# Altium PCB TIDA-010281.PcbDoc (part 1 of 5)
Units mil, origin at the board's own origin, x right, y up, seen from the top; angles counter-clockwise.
Board outline 3455.86 x 1121.8 mil, 8 copper layers (Top Layer, GND1, Sig1, PWR1, PWR2, Sig2, GND2, Bottom Layer), stack 59.155 mil thick; 291 components, 180 nets, 941 pads, 539 vias.
Unrouted connection lines stored in the file: 41.
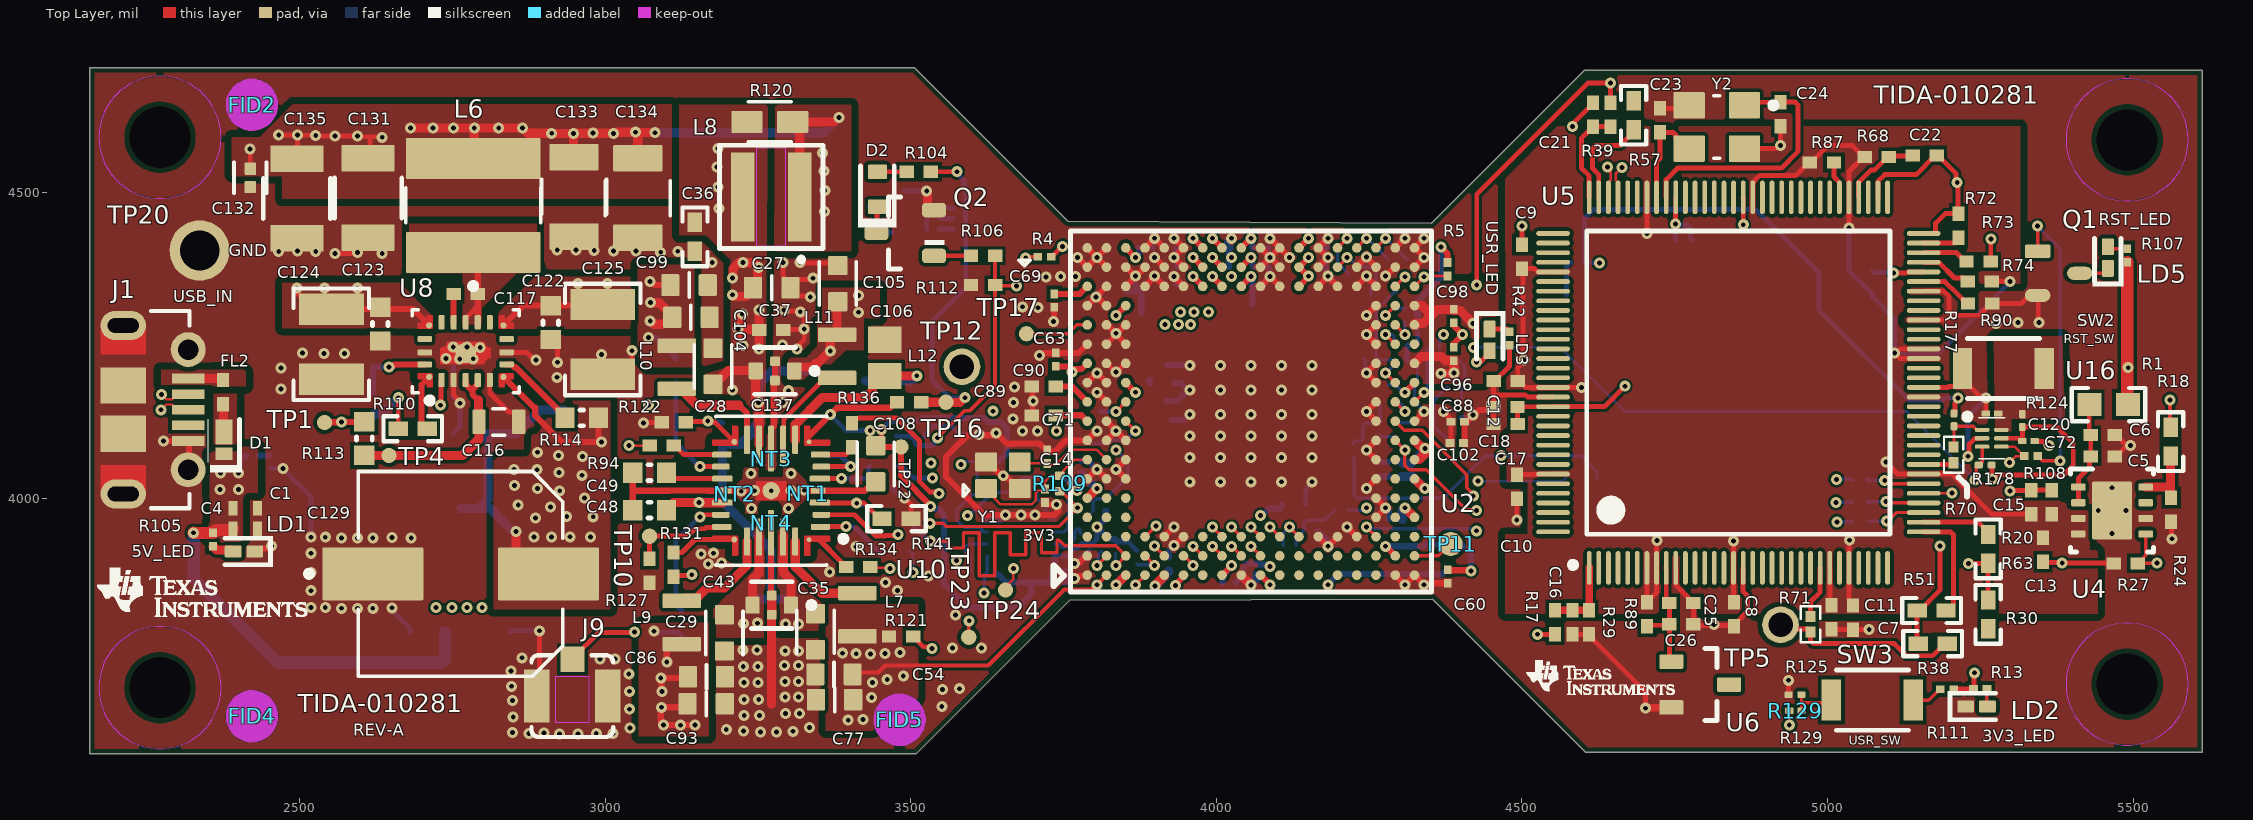
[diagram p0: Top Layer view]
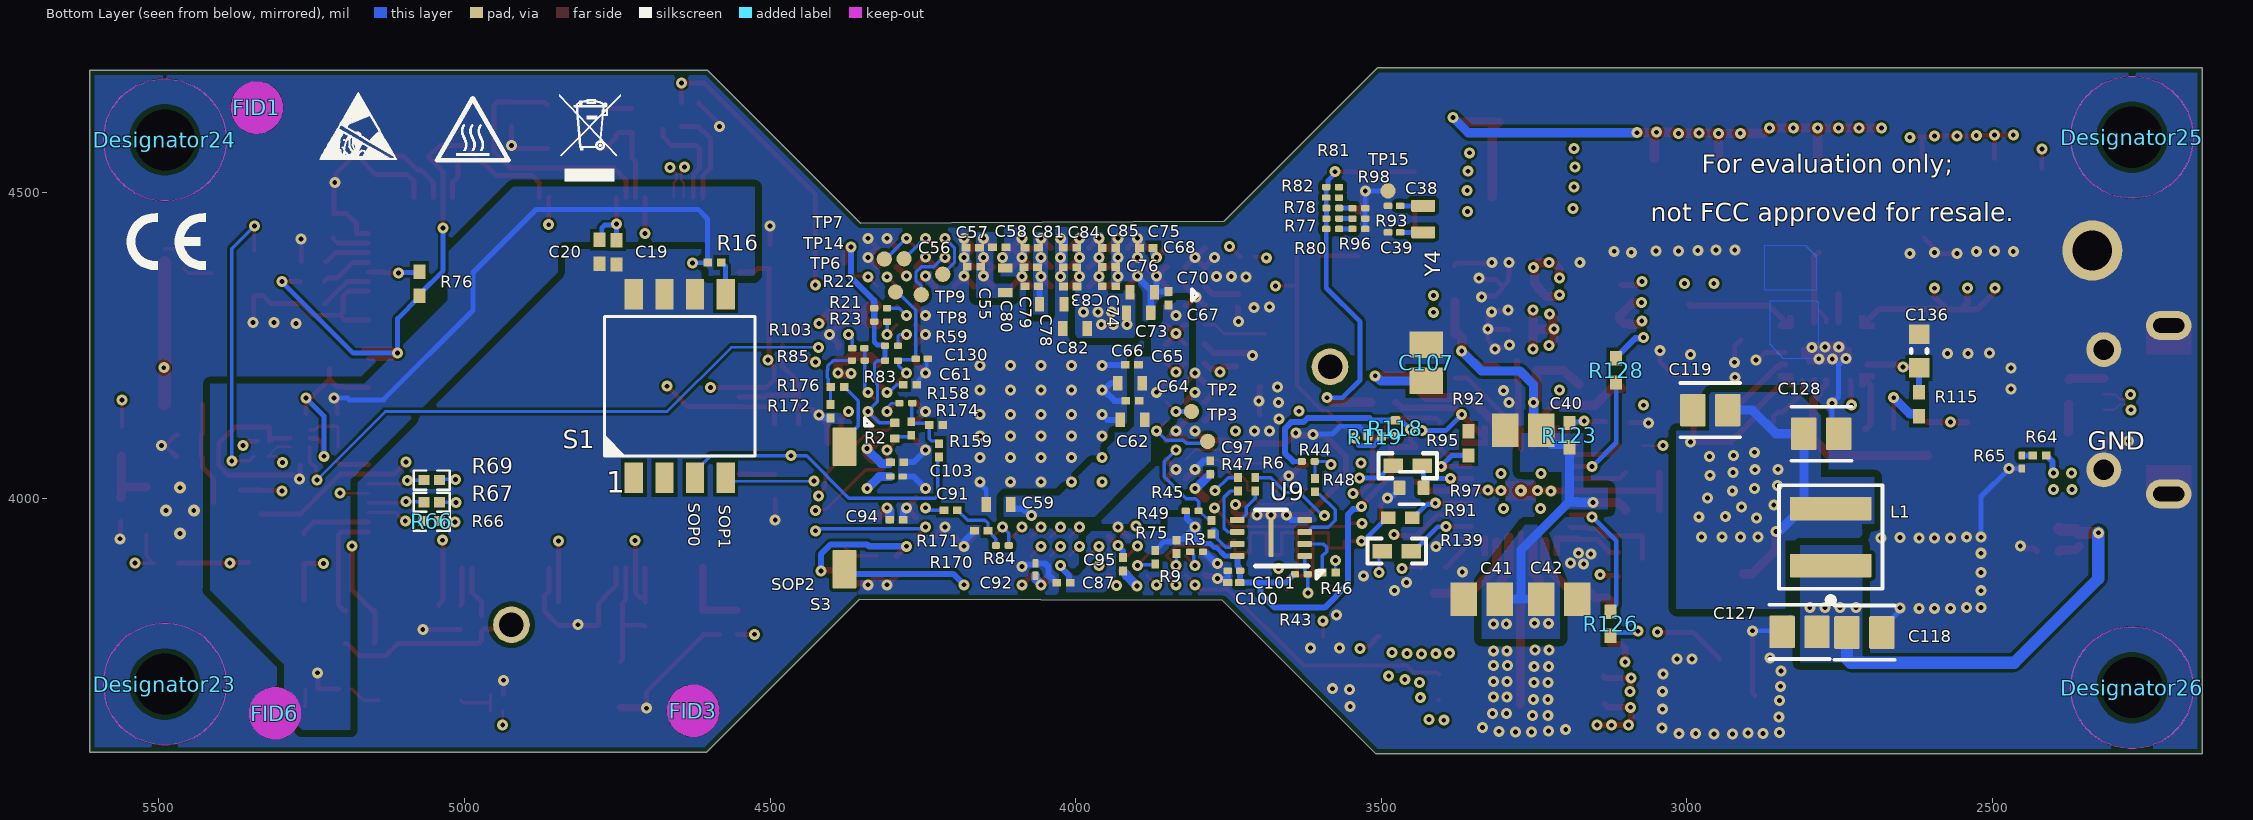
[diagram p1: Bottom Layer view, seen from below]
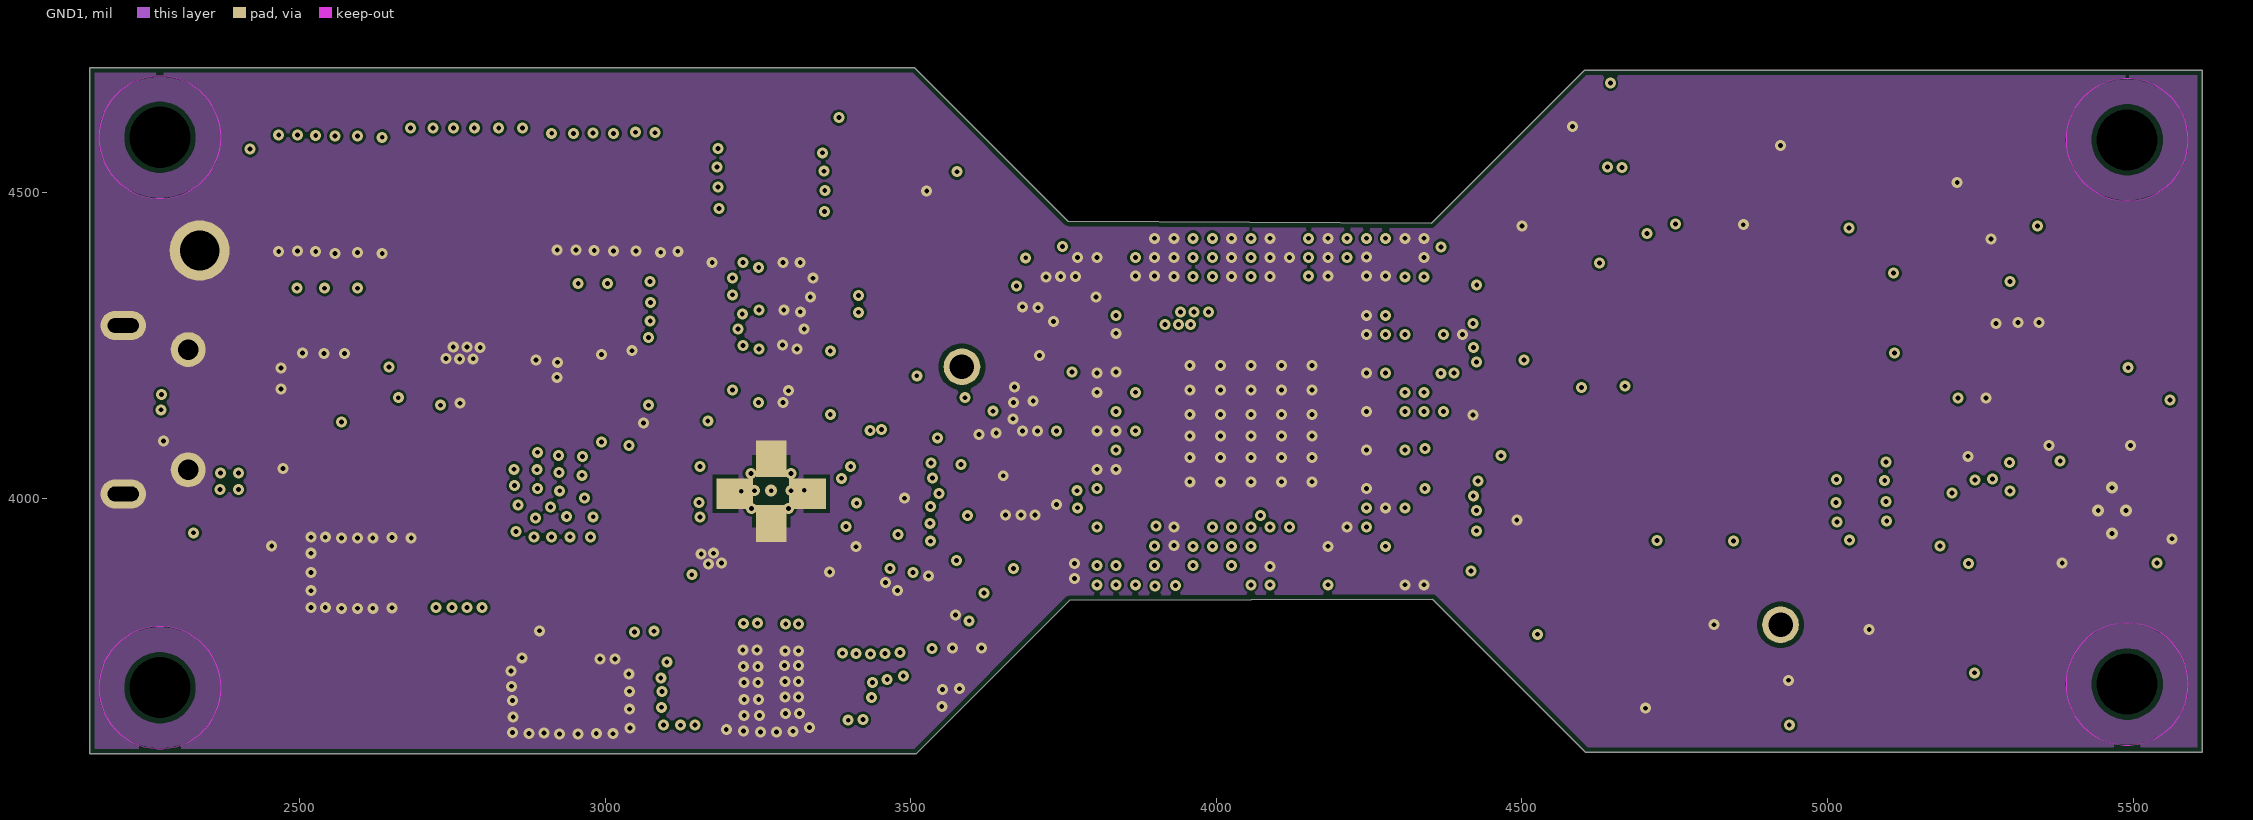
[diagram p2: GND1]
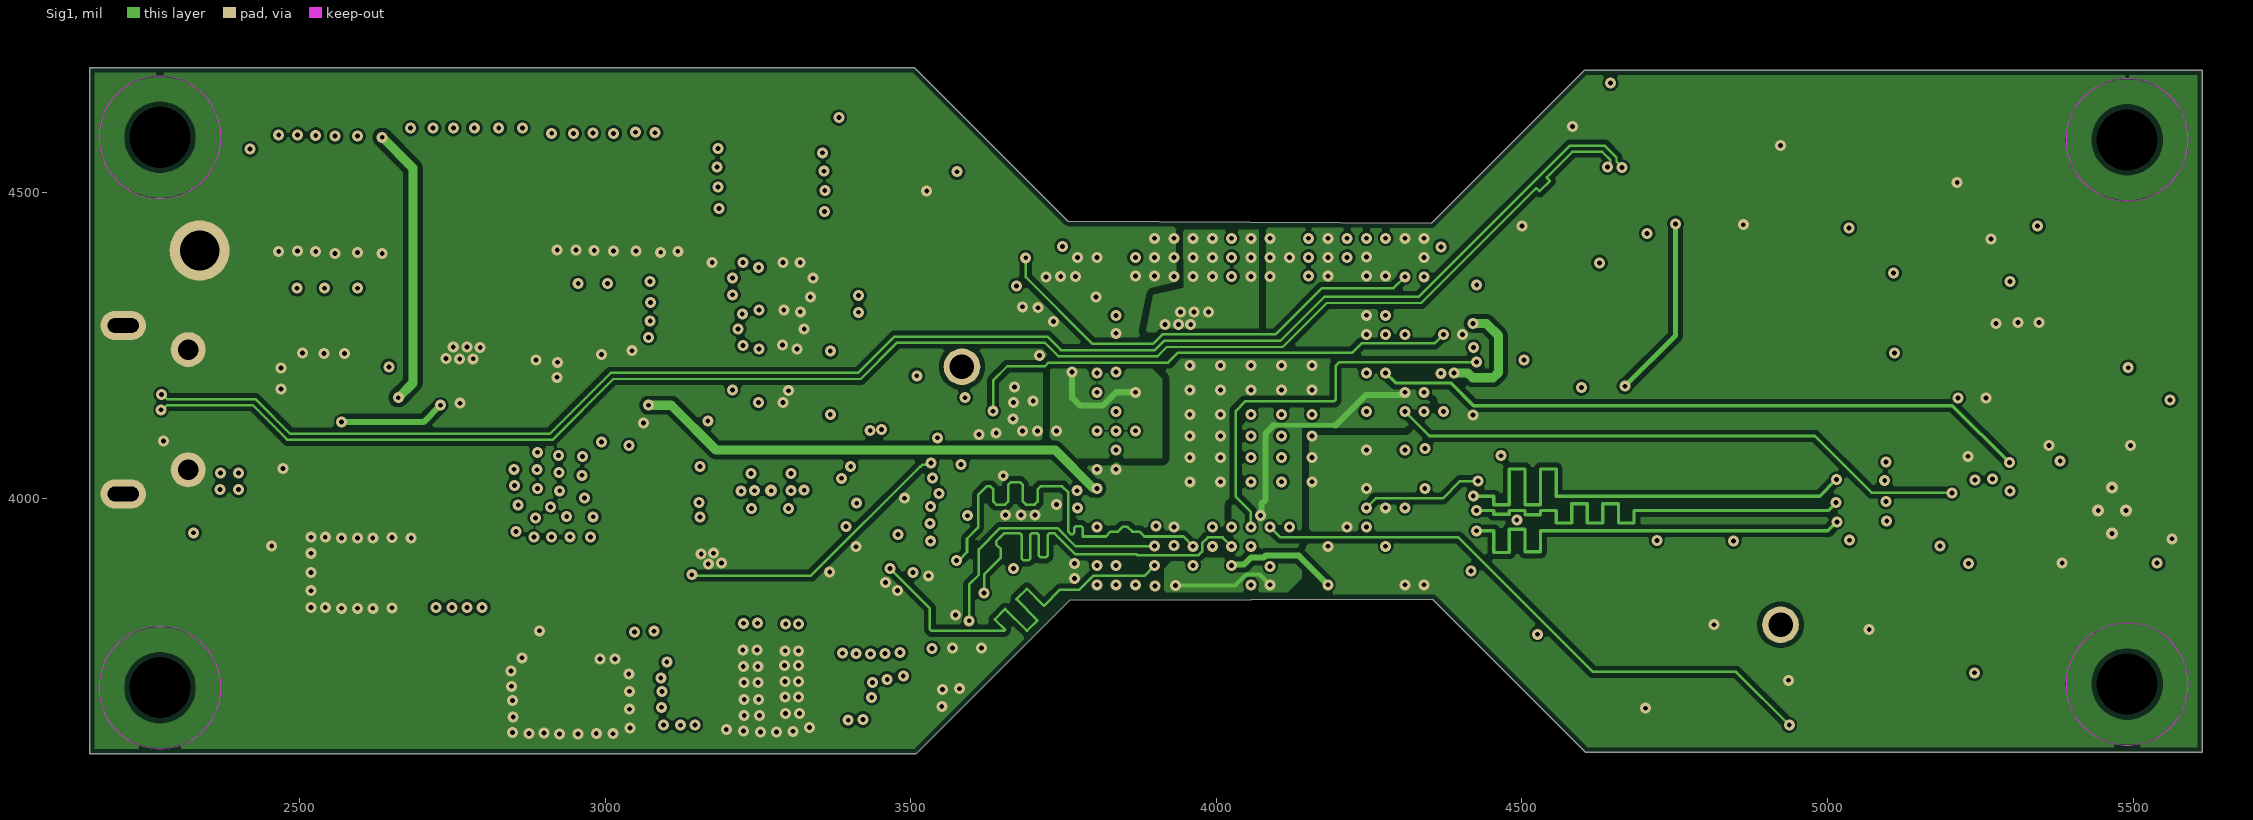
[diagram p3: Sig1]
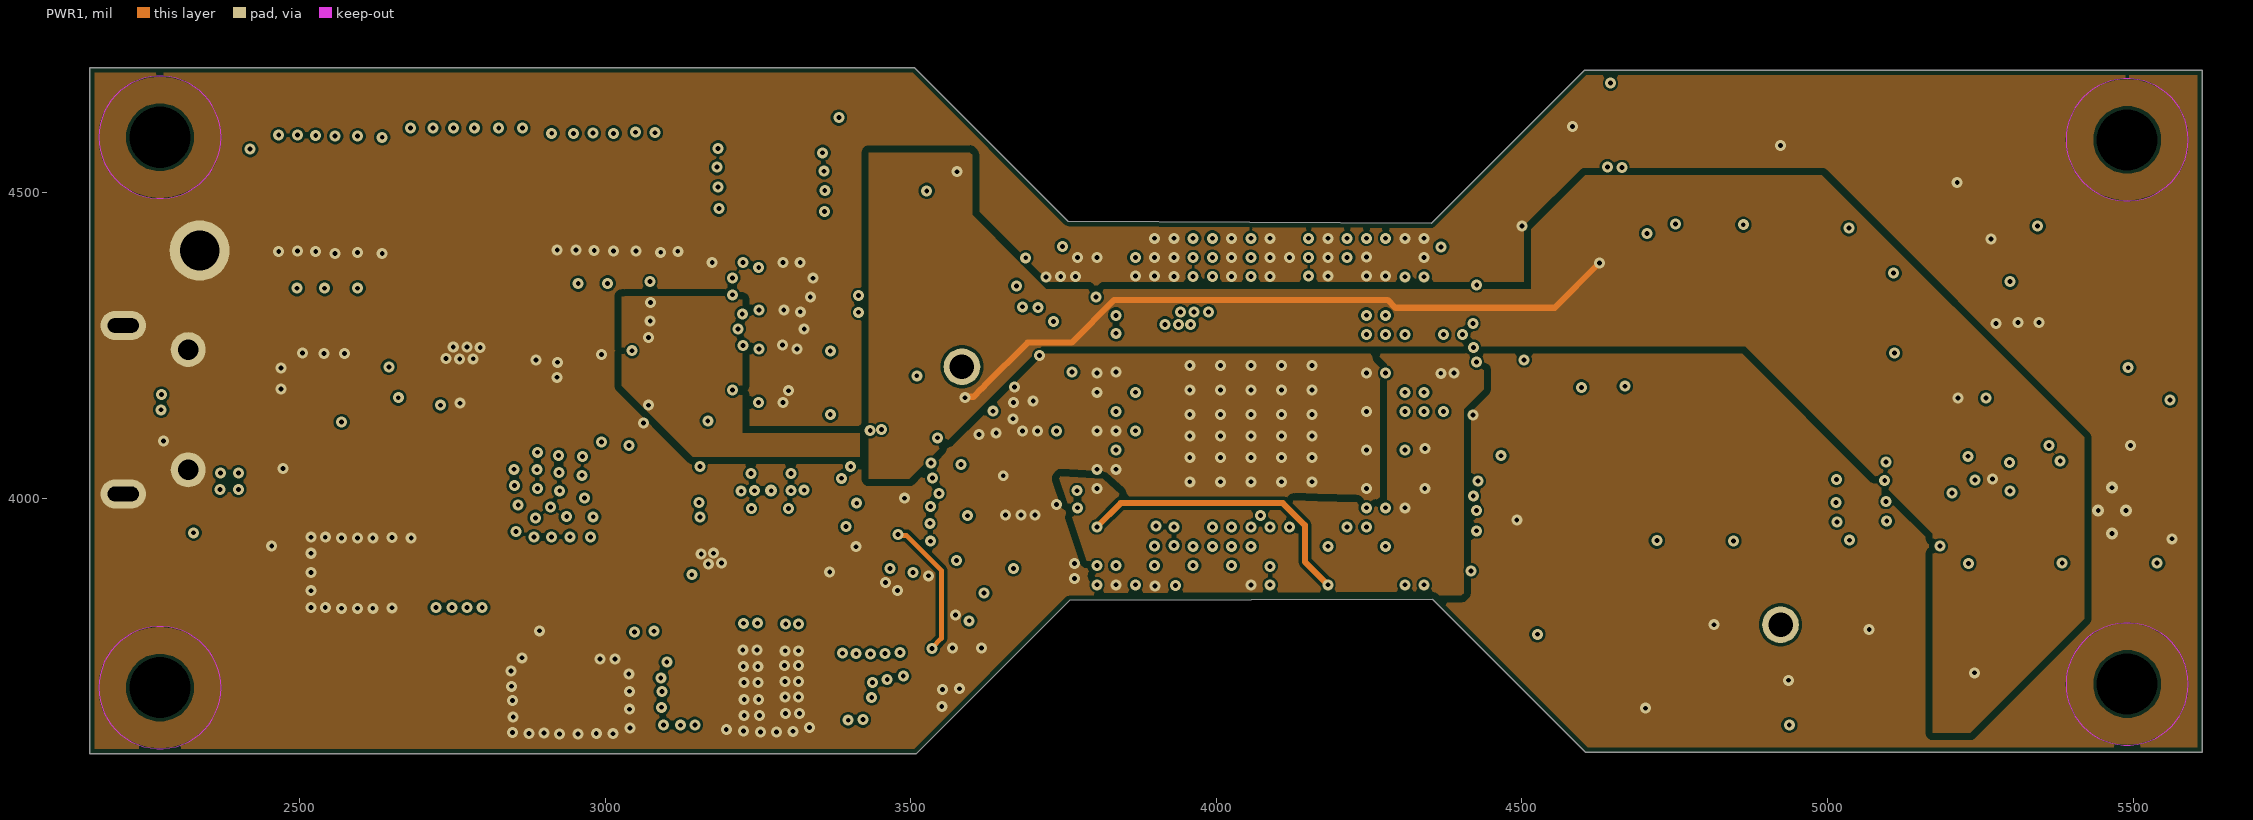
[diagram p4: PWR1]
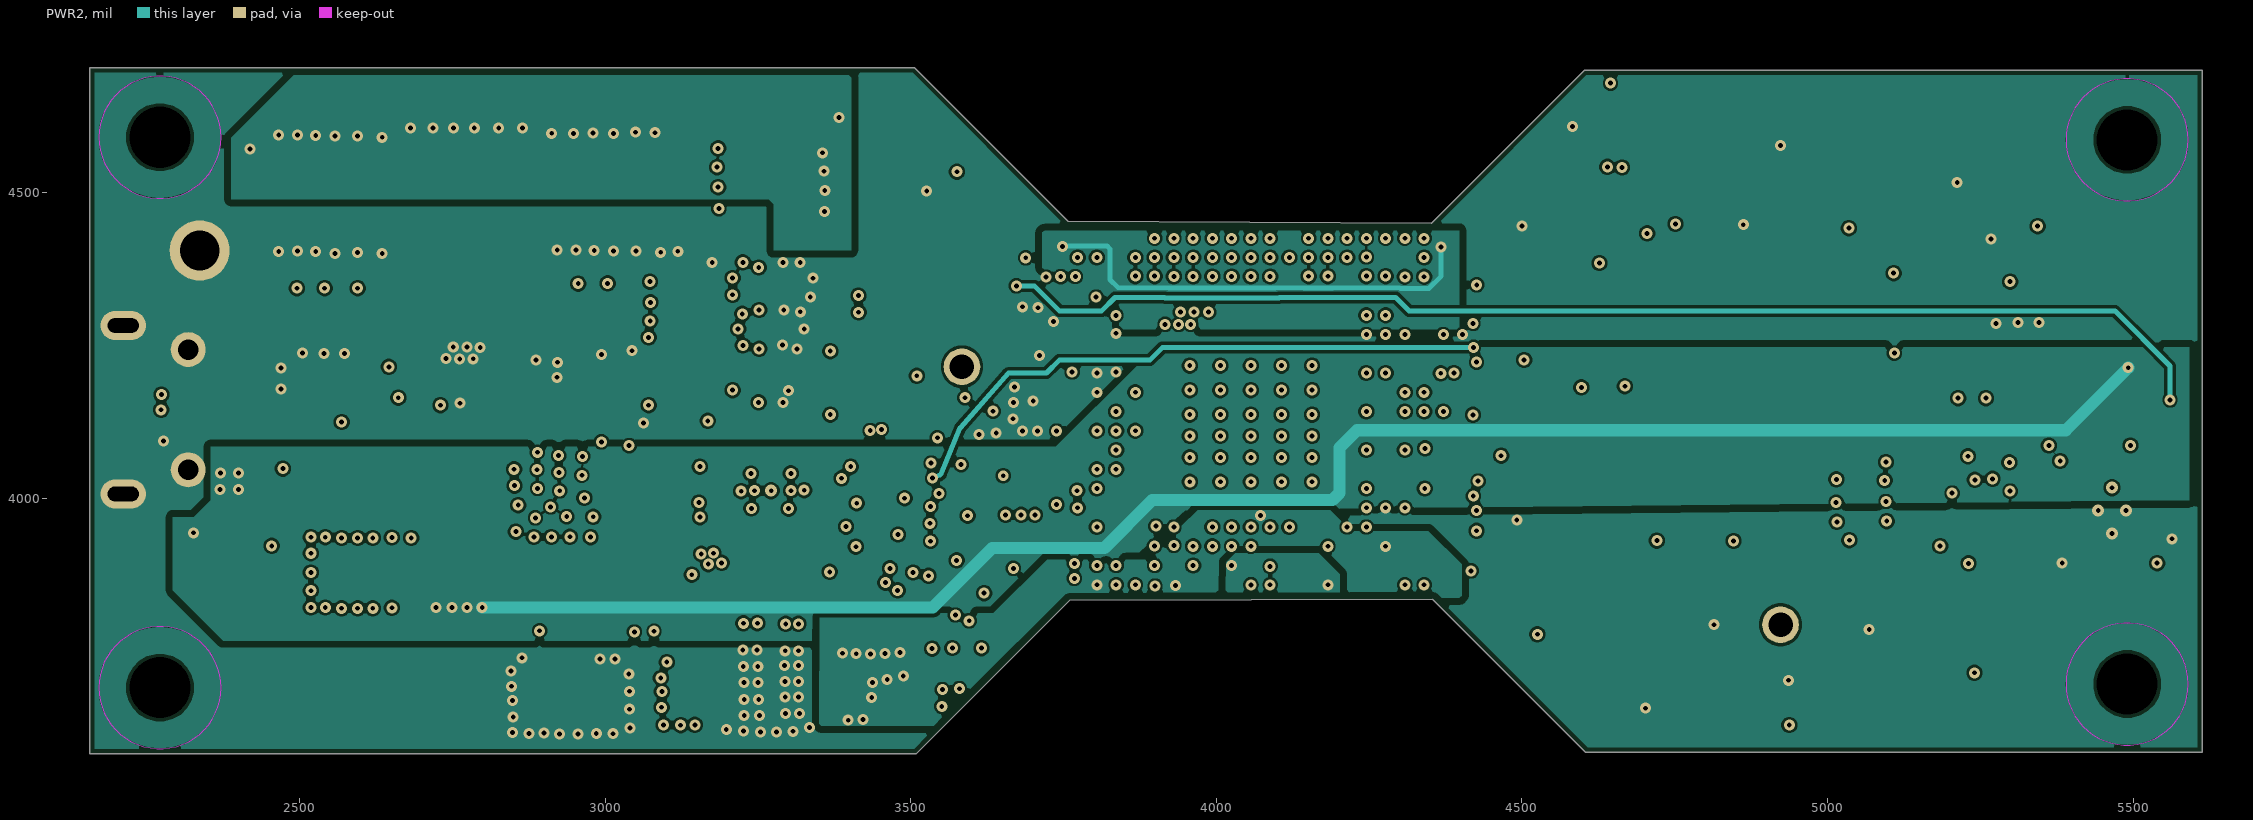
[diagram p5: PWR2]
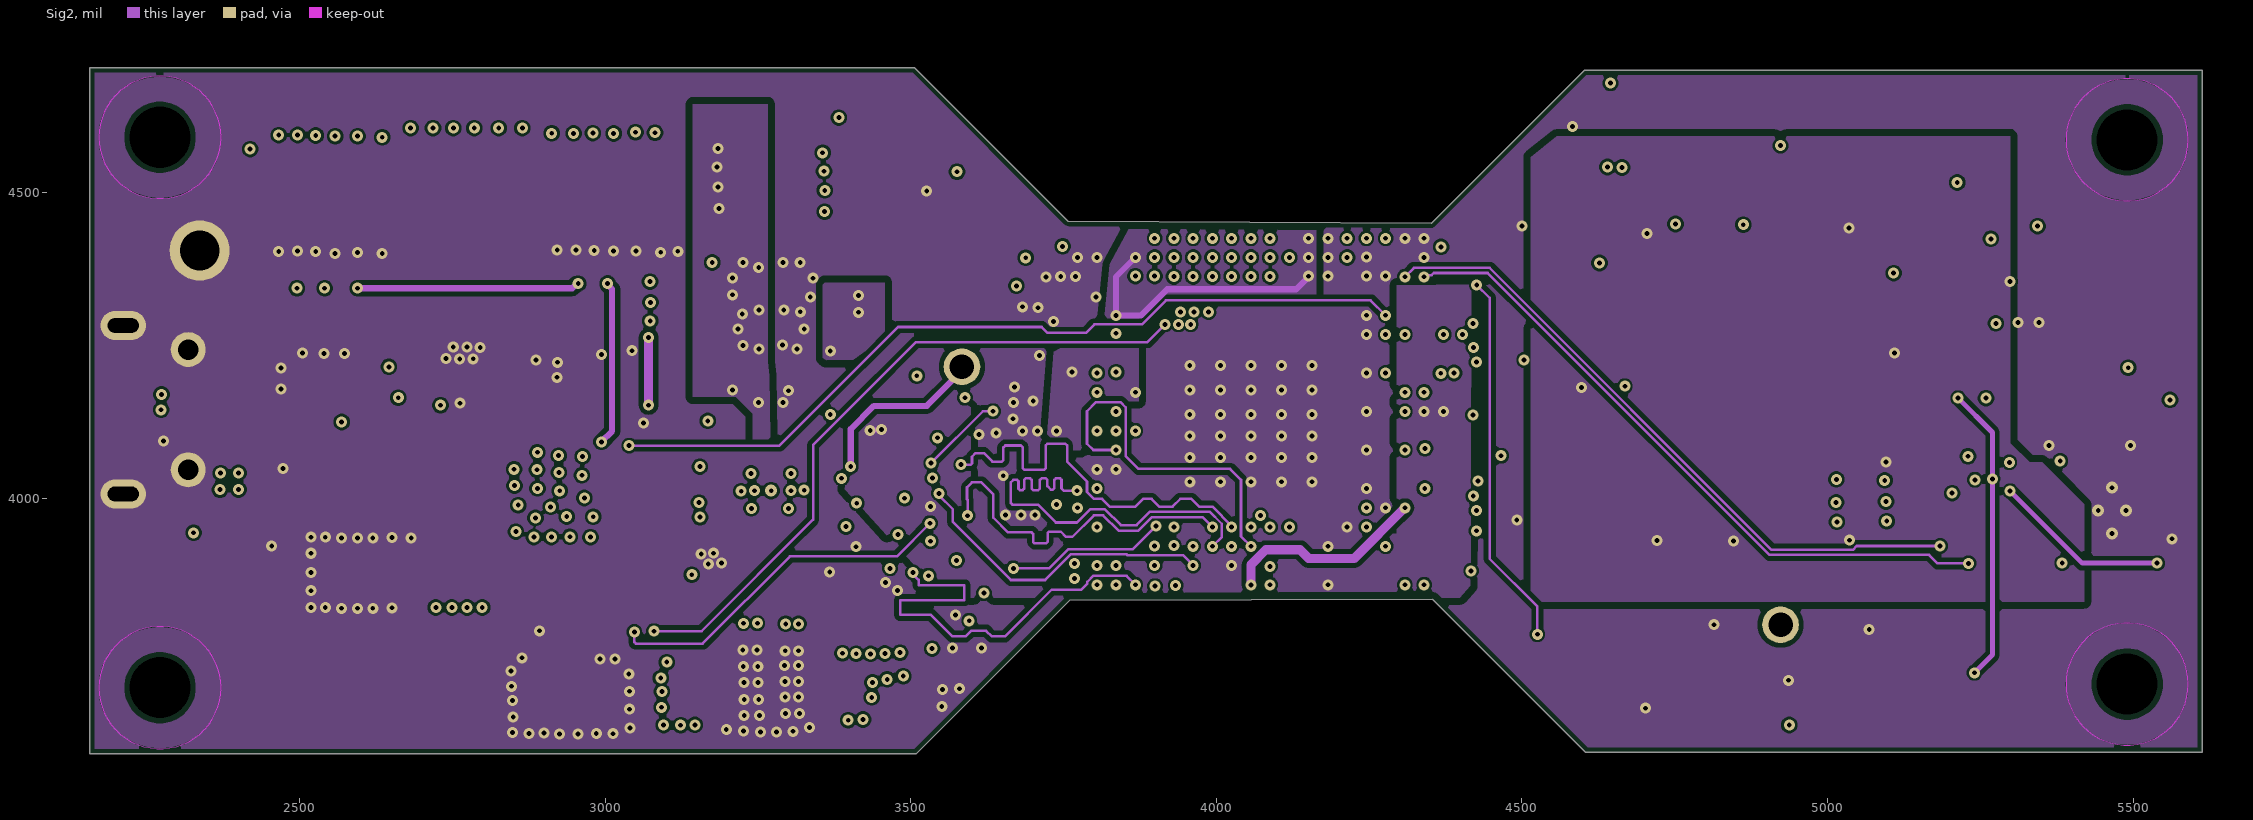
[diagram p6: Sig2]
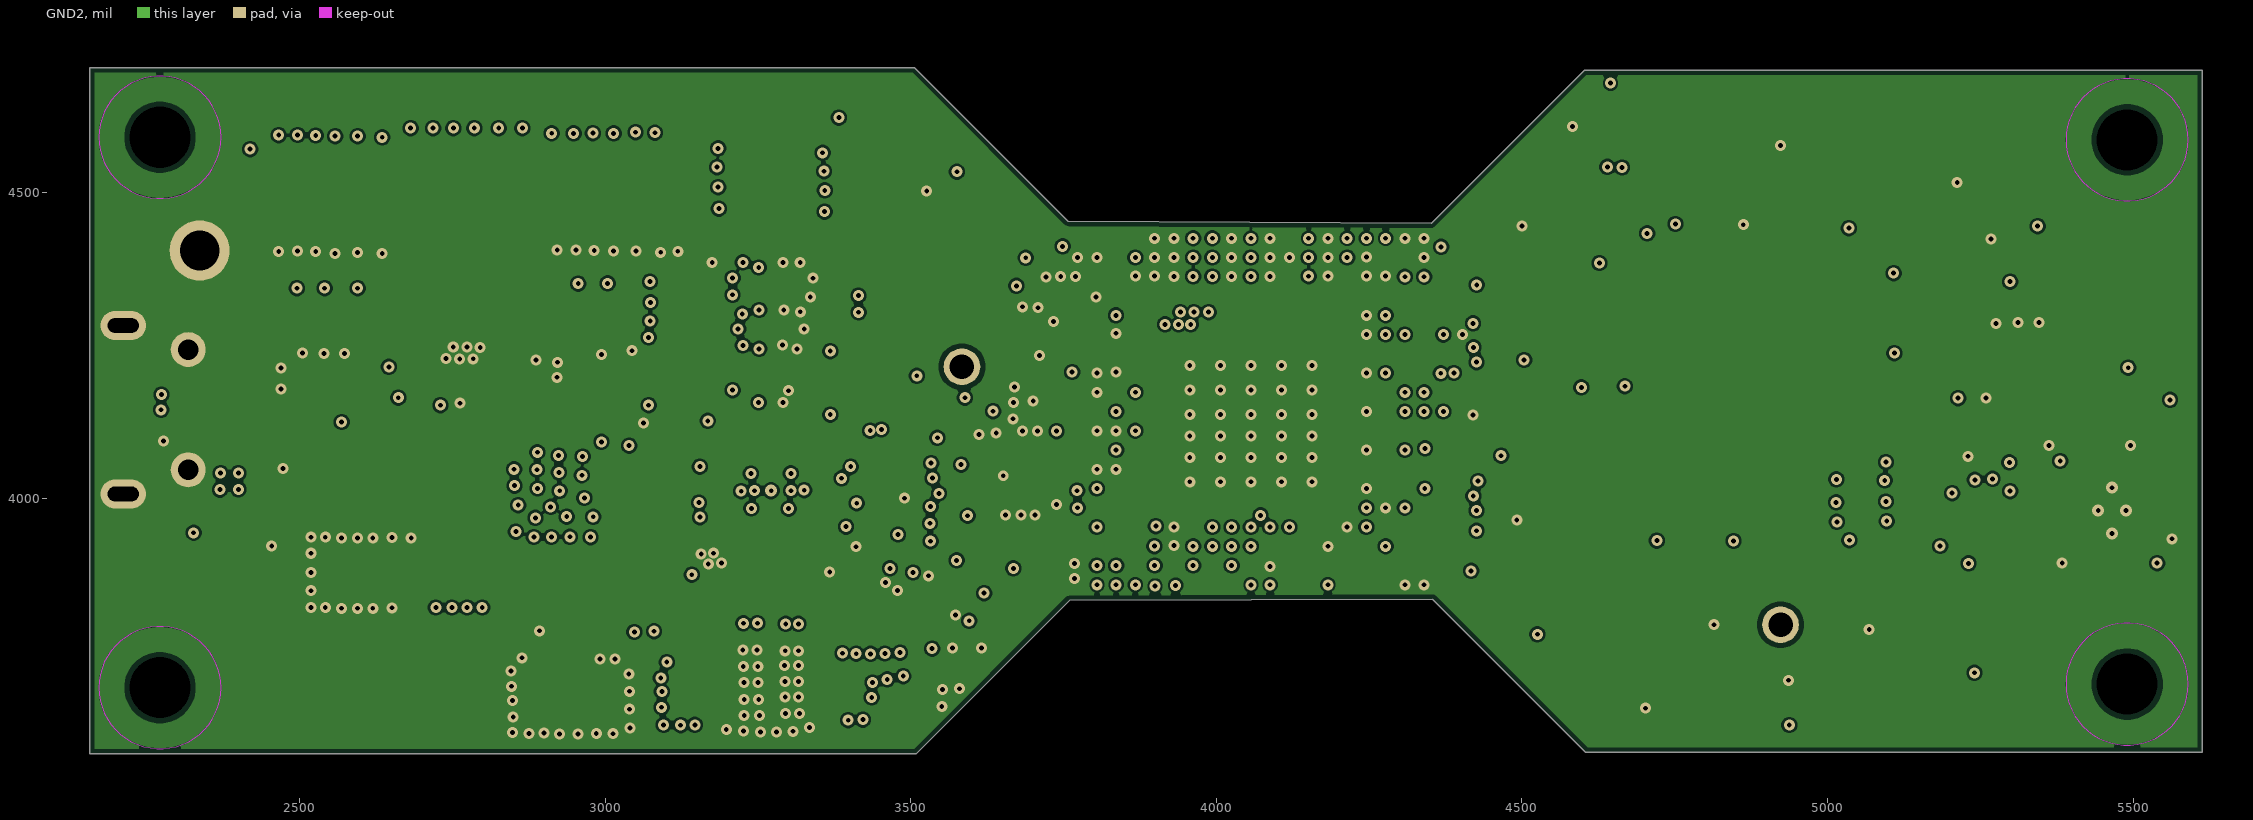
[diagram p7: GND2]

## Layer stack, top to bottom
Top Solder: solder mask 2, Solder Resist, Dk 4.4
Top Layer: signal copper 1.85
Dielectric1: core 1.462, FR-4 High Tg, Dk 3.832
Dielectric 2: core 2.224, FR-4 High Tg, Dk 3.832
GND1: signal copper 2.638
Dielectric3: dielectric 4, FR-4 High Tg, Dk 4.4
Sig1: signal copper 1.26
Dielectric4: dielectric 3.162, FR-4 High Tg, Dk 4.13
Dielectric 5: dielectric 3.162, FR-4 High Tg, Dk 4.13
Dielectric 6: dielectric 3.162, FR-4 High Tg, Dk 4.13
PWR1: signal copper 2.638
Dielectric7: dielectric 8, FR-4 High Tg, Dk 4.41
PWR2: signal copper 2.638
Dielectric8: dielectric 3.175, FR-4 High Tg, Dk 4.13
Dielectric 9: dielectric 3.175, FR-4 High Tg, Dk 4.13
Dielectric 10: dielectric 3.175, FR-4 High Tg, Dk 4.13
Sig2: signal copper 1.26
Dielectric11: dielectric 4, FR-4 High Tg, Dk 4.4
GND2: signal copper 2.638
Dielectric12: dielectric 2.224, FR-4 High Tg, Dk 3.832
Dielectric 13: dielectric 1.462, FR-4 High Tg, Dk 3.832
Bottom Layer: signal copper 1.85
Bottom Solder: solder mask 2, Solder Resist, Dk 4.4

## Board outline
2156.92,3582.01 2156.92,4703.8 3506.33,4703.8 3756.88,4453.25 3757.41,4452.93 4351.55,4449.43 4602.1,4699.98 5612.79,4699.98 5612.79,3583.92 4604.38,3583.92 4353.83,3834.47 3759.7,3832.55 3509.15,3582.01

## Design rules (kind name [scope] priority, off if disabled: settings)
AcuteAngle [All] p1: minimum=4.50000000000000E+0001 checktracksonly=TRUE
AssemblyTestPointUsage [All] p1: valid=2
BoardOutlineClearance BoardOutlineClearance_1 [InNet('GND')] p1: gap=8 ignorepadtopadclearanceinfootprint=FALSE
BoardOutlineClearance [All and (Not (OnLayer('Bottom Overlay') or OnLayer('Top Overlay') or InComponentClass('Fid')))] p2: gap=12 ignorepadtopadclearanceinfootprint=FALSE except(0: Text-OutlineEdge; 10: Via-OutlineEdge)
Clearance Clearance_fiducials [InComponentClass('FiducialMark')] p1: gap=0 ignorepadtopadclearanceinfootprint=FALSE
Clearance Keepout [(OnLayer('Keep-Out Layer'))] p2: gap=0.01 ignorepadtopadclearanceinfootprint=FALSE except(5.9: THPad-THPad; 7: Arc-THPad Track-THPad THPad-Via; 8: THPad-Fill THPad-Poly THPad-Region)
Clearance RF_TRACE [InNetClass('RF')] p3: gap=4 ignorepadtopadclearanceinfootprint=FALSE except(0: Arc-Hole Track-Hole SMDPad-Hole THPad-Hole Via-Hole Fill-Hole Poly-Hole Region-Hole Text-Hole; 2: Arc-Text Track-Text SMDPad-Text THPad-Text Via-Text Fill-Text Poly-Text Region-Text Text-Text; 5.9: THPad-THPad; 6: SMDPad-Fill SMDPad-Poly SMDPad-Region Via-Fill Via-Poly Via-Region; 7: Arc-THPad Track-THPad THPad-Via; 8: THPad-Fill THPad-Poly THPad-Region; 8.92: Arc-Fill Arc-Poly Arc-Region Track-Fill Track-Poly Track-Region; 15: Fill-Fill Fill-Poly Fill-Region Poly-Poly Poly-Region Region-Region)
Clearance AOP_T-B [WithinRoom('BGA') vs (OnLayer('Bottom Layer') or OnLayer('Top Layer'))] p4: gap=4 ignorepadtopadclearanceinfootprint=TRUE except(0: Arc-Hole Track-Hole SMDPad-Hole THPad-Hole Via-Hole Fill-Hole Poly-Hole Region-Hole Text-Hole; 3.8: SMDPad-Via; 3.9: Arc-Via Track-Via; 5.9: THPad-THPad; 7: Arc-THPad Track-THPad THPad-Via; 8: THPad-Fill THPad-Poly THPad-Region Fill-Fill Fill-Poly Fill-Region Poly-Poly Poly-Region Region-Region)
Clearance AOP_Sig [WithinRoom('BGA') vs (OnLayer('sig1') or OnLayer('sig2'))] p5: gap=4 ignorepadtopadclearanceinfootprint=FALSE except(0: Arc-Hole Track-Hole SMDPad-Hole THPad-Hole Via-Hole Fill-Hole Poly-Hole Region-Hole Text-Hole; 3.5: Arc-Arc Arc-Track Arc-Via Arc-Text Track-Track Track-Via Track-Text SMDPad-Text THPad-Text Via-Via Via-Text Fill-Text Poly-Text Region-Text Text-Text; 3.8: SMDPad-Via; 5.9: THPad-THPad; 7: Arc-THPad Track-THPad THPad-Via; 8: SMDPad-THPad THPad-Fill THPad-Poly THPad-Region; 15: Fill-Fill Fill-Poly Fill-Region Poly-Poly Poly-Region Region-Region)
Clearance 50E_INNERlayer [(OnLayer('sig1') or OnLayer('Sig2'))] p6: gap=4.2 ignorepadtopadclearanceinfootprint=TRUE except(0: Arc-Hole Track-Hole SMDPad-Hole THPad-Hole Via-Hole Fill-Hole Poly-Hole Region-Hole Text-Hole; 2: SMDPad-Text Fill-Text Poly-Text Region-Text Text-Text; 3.5: Arc-Via Track-Via; 5.9: THPad-THPad; 6: SMDPad-Fill SMDPad-Poly SMDPad-Region; 7: Arc-THPad Track-THPad THPad-Via; 8: Arc-Fill Arc-Poly Arc-Region Track-Fill Track-Poly Track-Region THPad-Fill THPad-Poly THPad-Region; 12: Fill-Fill Fill-Poly Fill-Region Poly-Poly Poly-Region Region-Region)
Clearance INNERlayer [(OnLayer('pwr1') or OnLayer('pwr2'))] p7: gap=8 ignorepadtopadclearanceinfootprint=TRUE except(0: Arc-Hole Track-Hole SMDPad-Hole THPad-Hole Via-Hole Fill-Hole Poly-Hole Region-Hole Text-Hole; 2: SMDPad-Text Fill-Text Poly-Text Region-Text Text-Text; 4: Via-Fill Via-Poly Via-Region; 4.2: Arc-Text Track-Text THPad-Text Via-Via Via-Text; 5: THPad-Fill THPad-Poly THPad-Region; 5.9: THPad-THPad; 6: Arc-Via Arc-Fill Arc-Poly Arc-Region Track-Via Track-Fill Track-Poly Track-Region; 7: THPad-Via; 12: Fill-Fill Fill-Poly Fill-Region Poly-Poly Poly-Region Region-Region)
Clearance 100E [InDifferentialPairClass('100E') vs (OnLayer('Sig1') or OnLayer('Sig2'))] p8: gap=8 ignorepadtopadclearanceinfootprint=FALSE except(0: Arc-Hole Track-Hole SMDPad-Hole THPad-Hole Via-Hole Fill-Hole Poly-Hole Region-Hole Text-Hole; 2: Arc-Text Track-Text THPad-Text Via-Text Fill-Text Poly-Text Region-Text Text-Text; 4: Arc-SMDPad Track-SMDPad SMDPad-SMDPad SMDPad-THPad SMDPad-Via SMDPad-Text Via-Fill Via-Poly Via-Region; 5: Arc-Via Track-Via; 5.9: THPad-THPad; 6: SMDPad-Fill SMDPad-Poly SMDPad-Region Fill-Fill Fill-Poly Fill-Region Poly-Poly Poly-Region Region-Region; 7: Arc-THPad Track-THPad THPad-Via; 16: Arc-Arc Arc-Track Track-Track)
Clearance 100E_1 [InDifferentialPairClass('100E') vs (OnLayer('Bottom Layer') or OnLayer('Top Layer'))] p9: gap=8 ignorepadtopadclearanceinfootprint=FALSE except(0: Arc-Hole Track-Hole SMDPad-Hole THPad-Hole Via-Hole Fill-Hole Poly-Hole Region-Hole Text-Hole; 2: Arc-Text Track-Text THPad-Text Via-Text Fill-Text Poly-Text Region-Text Text-Text; 4: Arc-SMDPad Track-SMDPad SMDPad-SMDPad SMDPad-THPad SMDPad-Via SMDPad-Text Via-Fill Via-Poly Via-Region; 5: Arc-Via Track-Via; 5.9: THPad-THPad; 6: SMDPad-Fill SMDPad-Poly SMDPad-Region Fill-Fill Fill-Poly Fill-Region Poly-Poly Poly-Region Region-Region; 7: Arc-THPad Track-THPad THPad-Via; 11: Arc-Arc Arc-Track Track-Track)
Clearance 90E_OUTSIDE [InDifferentialPairClass('90E') vs OnOutside] p10: gap=6 ignorepadtopadclearanceinfootprint=TRUE except(0: Arc-Hole Track-Hole SMDPad-Hole THPad-Hole Via-Hole Fill-Fill Fill-Poly Fill-Region Fill-Hole Poly-Poly Poly-Region Poly-Hole Region-Region Region-Hole Text-Hole; 2: Arc-Text Track-Text SMDPad-Text THPad-Text Via-Text Fill-Text Poly-Text Region-Text Text-Text; 3.8: SMDPad-Via; 4: Arc-SMDPad Track-SMDPad SMDPad-SMDPad Via-Via Via-Fill Via-Poly Via-Region; 4.5: Arc-Arc Arc-Track Arc-Via Track-Track Track-Via; 5.9: THPad-THPad; 7: Arc-THPad Track-THPad SMDPad-THPad THPad-Via; 8: THPad-Fill THPad-Poly THPad-Region)
Clearance [All] p11: gap=1 ignorepadtopadclearanceinfootprint=TRUE except(0: Arc-Hole Track-Hole SMDPad-Hole THPad-Hole Via-Hole Fill-Hole Poly-Hole Region-Hole Text-Hole; 3.8: SMDPad-Via; 3.9: Arc-Via Track-Via; 4: Arc-SMDPad Track-SMDPad SMDPad-SMDPad Via-Via Via-Fill Via-Poly Via-Region; 4.5: Arc-Arc Arc-Track Track-Track; 5: Arc-Fill Arc-Poly Arc-Region Track-Fill Track-Poly Track-Region; 5.9: THPad-THPad; 6: SMDPad-Fill SMDPad-Poly SMDPad-Region; 7: Arc-THPad Track-THPad SMDPad-THPad THPad-Via; 8: THPad-Fill THPad-Poly THPad-Region; 12: Fill-Fill Fill-Poly Fill-Region Poly-Poly Poly-Region Region-Region)
Clearance "SAME NET" [All] p12: gap=0 ignorepadtopadclearanceinfootprint=FALSE except(0.5: SMDPad-Text; 5.9: THPad-THPad)
ComponentClearance ComponentClearance_R199_187 [InComponent('J11') or InComponent('TP20')] p1: gap=-1 collisioncheckmode=3 verticalgap=10 showdistances=FALSE
ComponentClearance ComponentClearance_R188_204 [InComponent('R188') vs InComponent('R204')] p2: gap=-1 collisioncheckmode=3 verticalgap=10 showdistances=FALSE
ComponentClearance [All] p3: gap=1 collisioncheckmode=3 verticalgap=10 showdistances=FALSE
ComponentClearance ComponentClearance_MountingHoles_FiducialMarks [InComponentClass('Mounting Holes')  or InComponentClass('FiducialMark') vs InComponentClass('FiducialMark')] p4: gap=50 collisioncheckmode=3 verticalgap=10 showdistances=FALSE
ComponentClearance ComponentClearance_Shunt [InComponentClass('Header') vs InComponentClass('Shunt')] p5: gap=1 collisioncheckmode=3 verticalgap=0 showdistances=FALSE
ComponentClearance ComponentClearance_Logo [InComponentClass('Logo')] p6: gap=50 collisioncheckmode=3 verticalgap=10 showdistances=FALSE
ComponentClearance ComponentClearance_ScrewToNut [(HasFootprint('NY PMS 440 0025 PH')) vs (HasFootprint('Keystone_1902C'))] p7: gap=5 collisioncheckmode=3 verticalgap=10 showdistances=FALSE
ComponentClearance ComponentClearance_MountingHoles [InComponentClass('Mounting Holes')] p8: gap=20 collisioncheckmode=3 verticalgap=100000 showdistances=FALSE
ComponentClearance ComponentClearance_SmallPassives [HasFootprint('0201*') or HasFootprint('0402*') or HasFootprint('0508') or HasFootprint('0603*') or HasFootprint('0612') or HasFootprint('0805*') or HasFootprint('0815*') or HasFootprint('0830*') or HasFootprint('1206*') or HasFootprint('1210*') or HasFootprint('1808*') or HasFootprint('1812*') or HasFootprint('1825*') or HasFootprint('2010*') or HasFootprint('2220*') or HasFootprint('2225*') or HasFootprint('2512*') or HasFootprint('2728*') or HasFootprint('3518*') vs HasFootprint('0201*') or HasFootprint('0402*') or HasFootprint('0508') or HasFootprint('0603*') or HasFootprint('0612') or HasFootprint('0805*') or HasFootprint('0815*') or HasFootprint('0830*') or HasFootprint('1206*') or HasFootprint('1210*') or HasFootprint('1808*') or HasFootprint('1812*') or HasFootprint('1825*') or HasFootprint('2010*') or HasFootprint('2220*') or HasFootprint('2225*') or HasFootprint('2512*') or HasFootprint('2728*') or HasFootprint('3518*')] p9: gap=10 collisioncheckmode=3 verticalgap=10 showdistances=FALSE
ComponentClearance ComponentClearance_THtoSMT [IsThruComponent vs IsSMTComponent] p10: gap=5 collisioncheckmode=3 verticalgap=20 showdistances=FALSE
ComponentClearance ComponentClearance_THtoTH [IsThruComponent vs IsThruComponent] p11: gap=20 collisioncheckmode=3 verticalgap=30 showdistances=FALSE
DiffPairsRouting Diff_90E [InDifferentialPair('USB_net')] p1: maxlimit=100 minlimit=4.5 mostfreqgap=10 toplayer_maxgap=4.5 toplayer_prefgap=4.5 toplayer_minwidth=4 toplayer_maxwidth=4 toplayer_prefwidth=4 midlayer1_mingap=10 midlayer1_minwidth=15 midlayer1_maxwidth=15 midlayer1_prefwidth=15 midlayer2_mingap=6 midlayer2_maxgap=6 midlayer2_prefgap=6 midlayer2_minwidth=4 midlayer2_maxwidth=4 midlayer2_prefwidth=4 midlayer3_mingap=10 midlayer3_minwidth=15 midlayer3_maxwidth=15 midlayer3_prefwidth=15 midlayer6_mingap=10 midlayer6_minwidth=15 midlayer6_maxwidth=15 midlayer6_prefwidth=15 midlayer7_mingap=6 midlayer7_maxgap=6 midlayer7_prefgap=6 midlayer7_minwidth=4 midlayer7_maxwidth=4 midlayer7_prefwidth=4 midlayer8_mingap=10 midlayer8_minwidth=15 midlayer8_maxwidth=15 midlayer8_prefwidth=15 bottomlayer_maxgap=4.5 bottomlayer_prefgap=4.5 bottomlayer_minwidth=4 bottomlayer_maxwidth=4 bottomlayer_prefwidth=4 maxuncoupledlength=150
DiffPairsRouting Diff_100E [InDifferentialPairClass('100E')] p2: maxlimit=10 minlimit=7 mostfreqgap=10 toplayer_maxgap=7 toplayer_prefgap=7 toplayer_minwidth=4 toplayer_maxwidth=4 toplayer_prefwidth=4 midlayer1_mingap=10 midlayer1_minwidth=15 midlayer1_maxwidth=15 midlayer1_prefwidth=15 midlayer2_mingap=8 midlayer2_maxgap=8 midlayer2_prefgap=8 midlayer2_minwidth=3.5 midlayer2_maxwidth=3.5 midlayer2_prefwidth=3.5 midlayer3_mingap=10 midlayer3_minwidth=15 midlayer3_maxwidth=15 midlayer3_prefwidth=15 midlayer6_mingap=10 midlayer6_minwidth=15 midlayer6_maxwidth=15 midlayer6_prefwidth=15 midlayer7_mingap=8 midlayer7_maxgap=8 midlayer7_prefgap=8 midlayer7_minwidth=3.5 midlayer7_maxwidth=3.5 midlayer7_prefwidth=3.5 midlayer8_mingap=10 midlayer8_minwidth=15 midlayer8_maxwidth=15 midlayer8_prefwidth=15 bottomlayer_maxgap=7 bottomlayer_prefgap=7 bottomlayer_minwidth=4 bottomlayer_maxwidth=4 bottomlayer_prefwidth=4 maxuncoupledlength=500
DiffPairsRouting Diff_120E [InDifferentialPairClass('120E')] p3: maxlimit=10 minlimit=6.1 mostfreqgap=10 toplayer_maxgap=6.1 toplayer_prefgap=6.1 toplayer_minwidth=4 toplayer_maxwidth=4 toplayer_prefwidth=4 midlayer1_mingap=10 midlayer1_minwidth=15 midlayer1_maxwidth=15 midlayer1_prefwidth=15 midlayer2_mingap=10 midlayer2_minwidth=15 midlayer2_maxwidth=15 midlayer2_prefwidth=15 midlayer3_mingap=10 midlayer3_minwidth=15 midlayer3_maxwidth=15 midlayer3_prefwidth=15 midlayer6_mingap=10 midlayer6_minwidth=15 midlayer6_maxwidth=15 midlayer6_prefwidth=15 midlayer7_mingap=10 midlayer7_minwidth=15 midlayer7_maxwidth=15 midlayer7_prefwidth=15 midlayer8_mingap=10 midlayer8_minwidth=15 midlayer8_maxwidth=15 midlayer8_prefwidth=15 bottomlayer_maxgap=6.1 bottomlayer_prefgap=6.1 bottomlayer_minwidth=4 bottomlayer_maxwidth=4 bottomlayer_prefwidth=4 maxuncoupledlength=500
FabricationTestPointUsage TestPointUsage [All] p1: valid=2 allowmultiple=FALSE
FabricationTestpoint Testpoint [All] p1: side=3 testpointundercomponent=TRUE minsize=40 maxsize=100 preferedsize=60 minholesize=0 maxholesize=40 preferedholesize=32 testpointgrid=1 allowsidetop=TRUE allowsidebottom=TRUE usegrid=TRUE gridtolerance=0.01
FanoutControl Fanout_LCC [IsLCC] p1: bgadir=Out bgaviamode=Centered fanoutstyle=Auto fanoutdirection=Alternating viagrid=1 // Fanout_LCC (Default Rule)
FanoutControl Fanout_BGA [IsBGA] p2: bgadir=Out bgaviamode=Centered fanoutstyle=Auto fanoutdirection=Alternating viagrid=1 // Fanout_BGA (Default Rule)
FanoutControl Fanout_Default [All] p4: bgadir=Out bgaviamode=Centered fanoutstyle=Auto fanoutdirection=Alternating viagrid=1 // Fanout_Default (Default Rule)
FanoutControl Fanout_Small [(CompPinCount < 5)] p5: bgadir=Out bgaviamode=Centered fanoutstyle=Auto fanoutdirection=OutThenIn viagrid=1 // Fanout_Small (Default Rule)
HoleSize [All] p1: absolutevalues=TRUE maxlimit=251 minlimit=5.9 maxpercent=80.000 minpercent=20.000
MatchedLengths USB_1 [InNetClass('Diff_90E')] p1: tolerance=1000 checknetsindiffpair=FALSE checkdiffpairvsdiffpair=TRUE checkxsignals=TRUE checkothers=TRUE
MatchedLengths JTAG_1 [InNetClass('JTAG_1')] p2: tolerance=100 checknetsindiffpair=FALSE checkdiffpairvsdiffpair=TRUE checkxsignals=TRUE checkothers=TRUE
MatchedLengths QSPI_1 [InNetClass('QSPI_1')] p3: tolerance=50 checknetsindiffpair=FALSE checkdiffpairvsdiffpair=TRUE checkxsignals=TRUE checkothers=TRUE
MatchedLengths SPI_1 [InNetClass('SPI')] p4: tolerance=100 checknetsindiffpair=FALSE checkdiffpairvsdiffpair=TRUE checkxsignals=TRUE checkothers=TRUE
MatchedLengths [InNetClass('LVDS_IC')] p5: tolerance=20 checknetsindiffpair=FALSE checkdiffpairvsdiffpair=TRUE checkxsignals=TRUE checkothers=TRUE
MatchedLengths USB [InDifferentialPair('USB_net')] p6: tolerance=20 checknetsindiffpair=TRUE checkdiffpairvsdiffpair=FALSE checkxsignals=FALSE checkothers=FALSE
MatchedLengths QSPI [InxSignalClass('QSPI')] p7: tolerance=100 checknetsindiffpair=FALSE checkdiffpairvsdiffpair=TRUE checkxsignals=TRUE checkothers=TRUE
MatchedLengths SPI [InxSignalClass('SPI & HOSTINT')] p8: tolerance=200 checknetsindiffpair=FALSE checkdiffpairvsdiffpair=TRUE checkxsignals=TRUE checkothers=TRUE
MatchedLengths JTAG [InxSignalClass('JTAG')] p9: tolerance=100 checknetsindiffpair=FALSE checkdiffpairvsdiffpair=TRUE checkxsignals=TRUE checkothers=TRUE
MinimumAnnularRing MinimumAnnularRing_ThermalPadVias [IsVia and InAnyComponent] p1: minimumring=3
MinimumAnnularRing [All] p2: minimumring=3
MinimumSolderMaskSliver [All] p1: minsoldermaskwidth=2.5
PlaneConnect [All] p1: planeconnectstyle=Direct reliefexpansion=10 reliefentries=4 reliefconductorwidth=10 reliefairgap=10
PolygonConnect [All] p1: connectstyle=Direct reliefconductorwidth=10 reliefentries=4 polygonreliefangle="90 Angle" airgapwidth=10
RoutingVias [All] p1: holewidth=8 width=18 viastyle="Through Hole" minholewidth=7.87 minwidth=17 maxholewidth=40 maxwidth=30
RoutingVias ThermalPadVias [IsVia and InAnyComponent] p2: holewidth=7.87 width=19.68 viastyle="Through Hole" minholewidth=7.87 minwidth=19.68 maxholewidth=12.99 maxwidth=23.62
SilkToBoardRegionClearance [Not ((IsComment or IsDesignator) And (Hide <> 'False')) and not InRegion(1000,500,4000,800)] p1:
SilkToSilkClearance [All] p1: silktosilkclearance=0
SilkToSolderMaskClearance SilkToComponentPadClearance [(IsPad or IsFill or IsRegion) and InAnycomponent] p1: minsilkscreentomaskgap=3 clearancetoexposedcopper=TRUE
SilkToSolderMaskClearance "Silk to Solder Mask Opening" [All] p2: minsilkscreentomaskgap=3 clearancetoexposedcopper=FALSE
SolderMaskExpansion [All] p1: expansion=1.97 istentingtop=FALSE
SupplyNets "Schematic Supply Nets_18" [InNet('AR_1P0_RF2')] p1: voltage=0.000
SupplyNets "Schematic Supply Nets_17" [InNet('PMIC_5V0')] p2: voltage=0.000
SupplyNets "Schematic Supply Nets_16" [InNet('VCC_BA_3V3')] p3: voltage=0.000
SupplyNets "Schematic Supply Nets_14" [InNet('GND')] p4: voltage=0.000
SupplyNets "Schematic Supply Nets_13" [InNet('AR_1V8')] p5: voltage=0.000
SupplyNets "Schematic Supply Nets_12" [InNet('VDDC_1')] p6: voltage=0.000
SupplyNets "Schematic Supply Nets_11" [InNet('USB_5V')] p7: voltage=0.000
SupplyNets "Schematic Supply Nets_10" [InNet('PMIC_3V3')] p8: voltage=0.000
SupplyNets "Schematic Supply Nets_9" [InNet('AGND')] p9: voltage=0.000
SupplyNets "Schematic Supply Nets_8" [InNet('XDSET_1_VBUS')] p10: voltage=0.000
SupplyNets "Schematic Supply Nets_7" [InNet('5V_IN')] p11: voltage=0.000
SupplyNets "Schematic Supply Nets_6" [InNet('AR_1V4_SYNTH')] p12: voltage=0.000
SupplyNets "Schematic Supply Nets_5" [InNet('VCC_XDS_3V3')] p13: voltage=0.000
SupplyNets "Schematic Supply Nets_4" [InNet('AR_1P2')] p14: voltage=0.000
SupplyNets "Schematic Supply Nets_3" [InNet('PVIN3V3')] p15: voltage=0.000
SupplyNets "Schematic Supply Nets_2" [InNet('PMIC_INPUT3V3')] p16: voltage=0.000
SupplyNets "Schematic Supply Nets_1" [InNet('AR_1V4_APLL')] p17: voltage=0.000
SupplyNets "Schematic Supply Nets" [InNet('AR_VBGAP')] p18: voltage=0.000
Width RF [InNetClass('RF')] p1: maxlimit=100 minlimit=5.5 preferedwidth=10 toplayer_prefwidth=14.15 midlayer1_minwidth=10 midlayer1_maxwidth=10 midlayer2_minwidth=10 midlayer2_maxwidth=10 midlayer3_minwidth=10 midlayer3_maxwidth=10 midlayer6_minwidth=10 midlayer6_maxwidth=10 midlayer7_minwidth=10 midlayer7_maxwidth=10 midlayer8_minwidth=10 midlayer8_maxwidth=10 bottomlayer_minwidth=10 bottomlayer_maxwidth=10 minimp=50.000000 maximp=50.000000 favimp=50.000000
Width [All] p2: maxlimit=100 minlimit=4 preferedwidth=6 toplayer_maxwidth=40 toplayer_prefwidth=8 midlayer1_minwidth=4.2 midlayer1_maxwidth=20 midlayer1_prefwidth=4.2 midlayer2_minwidth=4.2 midlayer2_maxwidth=20 midlayer2_prefwidth=4.2 midlayer7_minwidth=4.2 midlayer7_maxwidth=20 midlayer7_prefwidth=4.2 midlayer8_minwidth=6 midlayer8_prefwidth=10 bottomlayer_maxwidth=40 bottomlayer_prefwidth=8 minimp=50.000000 maximp=50.000000 favimp=50.000000
15 further rules are at their usual default settings.

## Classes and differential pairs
net class JTAG_1: AR_TCK AR_TDI AR_TDO_SOP0 AR_TMS
net class QSPI_1: AR_QSPI_CLK AR_QSPI_CS AR_QSPI_D0 AR_QSPI_D1 AR_QSPI_D2 AR_QSPI_D3
net class SPI: AR_CS1 AR_MISO1 AR_MOSI1 AR_SPICLK1
net class Diff_90E: USB_DM USB_DP
component class PROC091G_XDS110_interface_1B: C21 C22 C23 C24 C25 C26 R38 R39 R51 R57 R63 R66 R67 R68 R69 R70 R71 R72 R73 R74 R76 R87 R89 R90 TP5 U5 U6 Y2
component class PROC091G_Hardware: Designator23 FID1 FID2 FID3 FID4 FID5 FID6 ZZ1 ZZ2 ZZ3 ZZ4 ZZ5.1 ZZ5.2
component class PROC091G_RST_SWITCH: C38 C39 C72 C120 LD2 LD3 LD5 Q1 R13 R42 R77 R78 R80 R81 R82 R93 R96 R98 R107 R108 R111 R124 R125 R129 R177 R178 SW2 SW3 TP15 TP20 U16 Y4
component class PROC091G_FLASH_USB_SOP: C1 C4 C100 C101 D1 FL2 J1 R6 R16 R43 R44 R45 R46 R47 R48 R49 R64 R65 S1 U9
component class PROC091G_PMIC_BUCK: C27 C28 C29 C35 C36 C37 C40 C41 C42 C43 C48 C49 C54 C77 C86 C93 C99 C104 C105 C106 C107 C108 C116 C117 C118 C119 C122 C123 C124 C125 C127 C128 C129 C131 C132 C133 C134 C135 C136 C137 D2 L1 L6 L7 L8 L9 L10 L11 L12 LD1 NT1 NT2 NT3 NT4 Q2 R91 R92 R94 R95 R97 R104 R105 R106 R110 R112 R113 R114 R115 R118 R119 R120 R121 R122 R123 R126 R127 R128 R131 R134 R136 R139 R141 TP1 TP4 TP10 TP12 TP16 TP22 U8 U10
component class PROC091G_XDS110_interface_1A: C5 C6 C7 C8 C9 C10 C11 C12 C13 C15 C16 C17 C18 C19 C20 R1 R17 R18 R20 R24 R27 R29 U4
component class PROC091G_AOP_PWR: C55 C56 C57 C58 C59 C60 C61 C62 C63 C64 C65 C66 C67 C68 C69 C70 C73 C74 C75 C76 C78 C79 C80 C81 C82 C83 C84 C85 C87 C88 C89 C90 C91 C92 C94 C95 C96 C97 C98 C102 C103 TP11
component class PROC091G_AOP_IO: C14 C71 C130 J9 R2 R3 R4 R5 R9 R21 R22 R23 R59 R75 R83 R84 R85 R103 R109 R158 R159 R170 R171 R172 R174 R176 S3 TP2 TP3 TP6 TP7 TP8 TP9 TP14 TP17 TP23 TP24 U2 Y1
component class FiducialMark: FID1 FID2 FID3 FID4 FID5 FID6
component class AssemblyNote: ZZ1 ZZ2 ZZ3 ZZ4 ZZ5.1 ZZ5.2
differential pair USB_net: +USB_DP -USB_DM

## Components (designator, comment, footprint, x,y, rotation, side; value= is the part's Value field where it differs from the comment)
C1 "CL05A106MP5NUNC" 0402_070 2411.06,3949.89 r180 top value=10uF
C4 "CL05A106MP5NUNC" 0402_070 2411.06,3983.16 r0 top value=10uF
C5 "C1005X7S1A225K050BC" 0402_065L 5450.26,4068.12 r0 top value=2.2uF
C6 "C0402C104K8RACTU" 0402L 5449.95,4103.44 r0 top value=0.1uF
C7 "C0402C104K8RACTU" 0402L 5041.78,3804.52 r90 top value=0.1uF
C8 "C0402C104K8RACTU" 0402L 4846.59,3809.65 r90 top value=0.1uF
C9 "GCM155R71E103KA37D" 0402L 4499.97,4395.09 r90 top value=0.01uF
C10 "C0402C104K8RACTU" 0402L 4491.53,4018.59 r90 top value=0.1uF
C11 "GRT155C81A105KE01D" 0402L 5006.67,3804.7 r270 top value=1uF
C12 "GRT155C81A105KE01D" 0402L 4473.4,4191.81 r180 top value=1uF
C13 "C1005X7S1A225K050BC" 0402_065L 5352.54,3915.52 r90 top value=2.2uF
C14 "GRM0335C1H4R7BA01D" 0201_033L 3719.55,4003.78 r90 top value=4.7pF
C15 "04025A150FAT2A" 0402L 5333.26,3993.37 r270 top value=15pF
C16 "GCM155R71E103KA37D" 0402L 4582.9,3796.66 r90 top value=0.01uF
C17 "C1005X7S1A225K050BC" 0402_065L 4473.13,4120.8 r0 top value=2.2uF
C18 "C0402C104K8RACTU" 0402L 4472.99,4148.91 r0 top value=0.1uF
C19 "C0402C104K8RACTU" 0402L 4751.4,4401.82 r90 bottom value=0.1uF
C20 "GRT155C81A105KE01D" 0402L 4778.85,4403.07 r270 bottom value=1uF
C21 "C0402C104K8RACTU" 0402L 4616.07,4627.32 r90 top value=0.1uF
C22 "C0402C104K8RACTU" 0402L 5158.73,4560.66 r180 top value=0.1uF
C23 "CC0402DRNPO9BN8R0" 0402L 4725.84,4617.95 r270 top value=8pF
C24 "CC0402DRNPO9BN8R0" 0402L 4923.05,4627.88 r90 top value=8pF
C25 "C0402C104K8RACTU" 0402L 4760.9,3828.66 r180 top value=0.1uF
C26 "GCM155R71E103KA37D" 0402L 4760.9,3793.56 r180 top value=0.01uF
C27 "GRM187R60J226ME15D" FP-GRM187R60J226ME15D_0603-MFG 3272.37,4344.32 r180 top value=22µF
C28 "885012106005" FP-885012106005_0603-MFG 3176.45,4215.57 r270 top value=4.7µF
C29 "885012106005" FP-885012106005_0603-MFG 3195.01,3779.46 r90 top value=4.7µF
C35 "885012106005" FP-885012106005_0603-MFG 3344.22,3781.31 r90 top value=4.7µF
C36 "GRM155R60J224KE01D" 0402 3146.87,4427.51 r270 top value=0.22uF
C37 "GCM155R71C104KA55D" 0402L 3271.56,4274.8 r0 top value=0.1uF
C38 "250R05L120JV4T" FP-250R05L120JV4T_0201-IPC_C 3478.91,4478.08 r0 bottom
C39 "250R05L120JV4T" FP-250R05L120JV4T_0201-IPC_C 3478.91,4434.78 r0 bottom
C40 "GCM21BR71A106KE22L" 0805L 3267.83,4110.72 r0 bottom value=10uF
C41 "GCM21BR71A106KE22L" 0805L 3335.53,3834.64 r0 bottom value=10uF
C42 "GCM21BR71A106KE22L" 0805L 3208.84,3834.64 r180 bottom value=10uF
C43 "NFM18HC105C1C3D" FP-NFM18HC105C1C3D_0603-MFG 3272.57,3824.82 r180 top
C48 "GCM188R70J225KE22D" 0603L 3072.69,3980.41 r0 top value=2.2uF
C49 "GCM188R70J225KE22D" 0603L 3072.69,4041.76 r0 top value=2.2uF
C54 "GRM187R60J226ME15D" FP-GRM187R60J226ME15D_0603-MFG 3374.45,3711.44 r0 top value=22µF
C55 "CL05A106MP5NUNC" 0402_070 4115.16,4356.5 r90 bottom value=10uF
C56 "LMK063BJ224MP-F" 0201_033L 4166.37,4378.24 r0 bottom value=0.22uF
C57 "LMK063BJ224MP-F" 0201_033L 4168.42,4409.4 r0 bottom value=0.22uF
C58 "LMK063BJ224MP-F" 0201_033L 4125.06,4410.16 r180 bottom value=0.22uF
C59 "CL05A106MP5NUNC" 0402_070 4126.24,3989.57 r0 bottom value=10uF
C60 "LMK063BJ224MP-F" 0201_033L 4378.33,3871.66 r270 top value=0.22uF
C61 "LMK063BJ224MP-F" 0201_033L 4270.98,4185.3 r180 bottom value=0.22uF
C62 "CL05A106MP5NUNC" 0402_070 3907,4128 r0 bottom value=10uF
C63 "LMK063BJ224MP-F" 0201_033L 3737.19,4226.49 r90 top value=0.22uF
C64 "LMK063BJ224MP-F" 0201_033L 3907,4159 r0 bottom value=0.22uF
C65 "CL05A106MP5NUNC" 0402_070 3911,4188 r0 bottom value=10uF
C66 "LMK063BJ224MP-F" 0201_033L 3908.02,4218 r0 bottom value=0.22uF
C67 "LMK063BJ224MP-F" 0201_033L 3848,4327 r90 bottom value=0.22uF
C68 "LMK063BJ224MP-F" 0201_033L 3884.37,4409.24 r0 bottom value=0.22uF
C69 "GRM033R61C473KE84D" 0201_033L 3734.67,4322.98 r270 top value=0.047uF
C70 "CL05A106MP5NUNC" 0402_070 3891,4337 r180 bottom value=10uF
C71 "GRM0335C1H4R7BA01D" 0201_033L 3723.07,4067.67 r270 top value=4.7pF
C72 "GRM033R6YA104KE14D" "FP-GRM033R6YA104KE14D_0201 (0603 Metric)-IPC_C" 5328.67,4093.48 r180 top
C73 "CL05A106MP5NUNC" 0402_070 3897,4303 r180 bottom value=10uF
C74 "CL03A225MQ3CRNC" 0201L 3945.46,4346.38 r180 bottom value=2.2uF
C75 "LMK063BJ224MP-F" 0201_033L 3945.46,4409.24 r180 bottom value=0.22uF
C76 "LMK063BJ224MP-F" 0201_033L 3945.46,4377.91 r180 bottom value=0.22uF
C77 "GRM187R60J226ME15D" FP-GRM187R60J226ME15D_0603-MFG 3375.33,3670.07 r0 top value=22µF
C78 "CL05A106MP5NUNC" 0402_070 4038.9,4317.13 r180 bottom value=10uF
C79 "CL03A225MQ3CRNC" 0201L 4071.88,4346.34 r0 bottom value=2.2uF
C80 "LMK063BJ224MP-F" 0201_033L 4073.37,4377.75 r0 bottom value=0.22uF
C81 "LMK063BJ224MP-F" 0201_033L 4071.88,4409.36 r0 bottom value=0.22uF
C82 "CL05A106MP5NUNC" 0402_070 4001.02,4277.32 r0 bottom value=10uF
C83 "CL03A225MQ3CRNC" 0201L 4008.9,4346.15 r0 bottom value=2.2uF
C84 "LMK063BJ224MP-F" 0201_033L 4009.24,4377.83 r0 bottom value=0.22uF
C85 "LMK063BJ224MP-F" 0201_033L 4009.24,4409.33 r0 bottom value=0.22uF
C86 "GRM187R60J226ME15D" FP-GRM187R60J226ME15D_0603-MFG 3165.73,3707.64 r180 top value=22µF
C87 "LMK063BJ224MP-F" 0201_033L 4019.98,3861.38 r0 bottom value=0.22uF
C88 "LMK063BJ224MP-F" 0201_033L 4394.91,4124.76 r0 top value=0.22uF
C89 "CGB2A1X6S0J105K033BC" 0402L 3717.5,4135.45 r180 top value=1uF
C90 "CGB2A1X6S0J105K033BC" 0402L 3717.37,4182.85 r180 top value=1uF
C91 "GRM033R6YA104KE14D" "FP-GRM033R6YA104KE14D_0201 (0603 Metric)-IPC_C" 4292.99,4035.17 r180 bottom
C92 "GRM033R6YA104KE14D" "FP-GRM033R6YA104KE14D_0201 (0603 Metric)-IPC_C" 4065.74,3883.1 r90 bottom
C93 "GRM187R60J226ME15D" FP-GRM187R60J226ME15D_0603-MFG 3165.11,3663.53 r180 top value=22µF
C94 "LMK063BJ224MP-F" 0201_033L 4293.19,3964.68 r180 bottom value=0.22uF
C95 "LMK063BJ224MP-F" 0201_033L 3922.37,3891.76 r90 bottom value=0.22uF
C96 "LMK063BJ224MP-F" 0201_033L 4388.37,4235.76 r90 top value=0.22uF
C97 "LMK063BJ224MP-F" 0201_033L 3779.79,4050.2 r90 bottom value=0.22uF
C98 "LMK063BJ224MP-F" 0201_033L 4388.37,4297.76 r270 top value=0.22uF
C99 "GRM187R60J226ME15D" FP-GRM187R60J226ME15D_0603-MFG 3137.28,4348.49 r180 top value=22µF
C100 "CL03A105MO3NRNH" FP-CL03A105MO3NRNH_0201-IPC_C 3741.24,3861.69 r0 bottom
C101 "GRM033R6YA104KE14D" "FP-GRM033R6YA104KE14D_0201 (0603 Metric)-IPC_C" 3741,3881.17 r0 bottom
C102 "CL03A225MQ3CRNC" 0201L 4393.22,4090.26 r0 top value=2.2uF
C103 "CL03A225MQ3CRNC" 0201L 4291.98,4058.8 r180 bottom value=2.2uF
C104 "GRM187R60J226ME15D" FP-GRM187R60J226ME15D_0603-MFG 3140.24,4295.6 r180 top value=22µF
C105 "885012106005" FP-885012106005_0603-MFG 3380.58,4350.88 r270 top value=4.7µF
C106 "GCM21BR71A106KE22L" 0805L 3457.62,4229.24 r90 top value=10uF
C107 "GCM21BR71A106KE22L" 0805L 3426.34,4221.13 r90 bottom value=10uF
C108 "885012106005" FP-885012106005_0603-MFG 3442.7,4056.02 r90 top value=4.7µF
C116 "CVCC" FP-CGA3E1X7R1C105M080AC_0603-IPC_C 2825.95,4124.7 r0 top value=1µF
C117 "Cboot" 0402L 2771.82,4333.75 r180 top value=0.1uF
C118 "GRM21BD72A225ME01K" FP-GRM21BD72A225ME01K_0805-IPC_C 2709.48,3780 r0 bottom locked value=2.2µF
C119 "GRM21BD72A225ME01K" FP-GRM21BD72A225ME01K_0805-IPC_C 2961.66,4143.96 r180 bottom value=2.2µF
C120 "GRM033R6YA104KE14D" "FP-GRM033R6YA104KE14D_0201 (0603 Metric)-IPC_C" 5269.13,4138.44 r180 top
C122 "HMK107B7104KAHT" 0603L 2910.99,4287.02 r270 top value=0.1uF
C123 "HMK107B7104KAHT" 0603L 2631.91,4284.74 r270 top value=0.1uF
C124 "CGA6M3X7S2A475K200AB" 1210_220 2551.86,4251.65 r270 top value=4.7uF
C125 "CGA6M3X7S2A475K200AB" 1210_220 2996.02,4259.51 r270 top value=4.7uF
C127 "GRM21BD72A225ME01K" FP-GRM21BD72A225ME01K_0805-IPC_C 2815.5,3780.99 r180 bottom locked value=2.2µF
C128 "GRM21BD72A225ME01K" FP-GRM21BD72A225ME01K_0805-IPC_C 2779.95,4105.2 r0 bottom value=2.2µF
C129 "A767KS336M1KLAE045" FP-A767KS336M1KLAE045_RADIAL-MFG 2763.49,3876.06 r0 top value=33µF
C130 "GRM033R6YA104KE14D" "FP-GRM033R6YA104KE14D_0201 (0603 Metric)-IPC_C" 4251.69,4228 r180 bottom
C131 "CGA6P1X7R1C226M250AC" 1210_280 2611.98,4490.85 r270 top value=22uF
C132 "Cohf" FP-GRM155R71E104KE14J_0402-IPC_C 2419.33,4523.93 r90 top value=100nF
C133 "GRM32EC81C476KE15K" FP-GRM32EC81C476KE15K_1210-MFG 2948.98,4492.76 r90 top value=47µF
C134 "GRM32EC81C476KE15K" FP-GRM32EC81C476KE15K_1210-MFG 3053.4,4490.88 r90 top value=47µF
C135 "CGA6P1X7R1C226M250AC" 1210_280 2495.65,4490.32 r270 top value=22uF
C136 "Cbias" 0603L 2620.02,4240.61 r90 bottom value=0.1uF
C137 "NFM18HC105C1C3D" FP-NFM18HC105C1C3D_0603-MFG 3277.88,4208.15 r180 top
D1 "NSR20F30NXT5G" DSN2_0603 2376.25,4097.33 r90 top value=30V
D2 "TLMY1000-GS08" TLMx1000_Yellow 3445.38,4505.37 r270 top value=Yellow
Designator23 "Comment" MHNP_2-5 5490.22,3695.67 r90 bottom
Designator24 "Comment" MHNP_2-5 5490.22,4586.13 r90 bottom
Designator25 "Comment" MHNP_2-5 2271.54,4590.27 r90 bottom
Designator26 "Comment" MHNP_2-5 2271.53,3689.79 r90 bottom
FID1 "Fiducial" Fiducial6.4-20 5339.66,4638.79 r90 bottom
FID2 "Fiducial" Fiducial6.4-20 2422.17,4643.42 r90 top
FID3 "Fiducial" Fiducial6.4-20 4625.75,3652.08 r90 bottom
FID4 "Fiducial" Fiducial6.4-20 2422.17,3643 r90 top
FID5 "Fiducial" Fiducial6.4-20 3481.66,3637.15 r90 top
FID6 "Fiducial" Fiducial6.4-20 5309.97,3647.95 r90 bottom
FL2 "BLM15PD300SZ1D" 0402L 2374.88,4173.51 r270 top
J1 "105017-0001" CONN_105017-0001 2264.58,4144.53 r270 top
J9 "U.FL-R-SMT-1(01)" CONN_UFL-R-SMT-1 2946.25,3676.11 r270 top
L1 "XGL4030-152MEC" FP-XGL4030-152MEC_SMT2_4MM0_4MM0-MFG 2764.49,3936.2 r90 bottom value=1.5uH
L6 "74438366010" FP-74438366010_SMT_IND_5MM4_5MM4-MFG 2784.02,4478.76 r90 top value=1uH
L7 "TFM201610ALMAR47MTAA" TFM201610ALMA 3412.67,3809.07 r270 top value=470nH
L8 "74438357047" WE-MAPI_4030 3271.56,4492.76 r180 top
L9 "TFM201610ALMAR47MTAA" TFM201610ALMA 3125.31,3796.57 r270 top value=470nH
L10 "TFM201610ALMAR47MTAA" TFM201610ALMA 3117.04,4213.98 r90 top value=470nH
L11 "TFM201610ALMA1R5MTAA" TFM201610ALMA 3379.44,4231.99 r90 top value=1.5uH
L12 "BLM15PD300SZ1D" 0402L 3497.13,4156.76 r0 top
LD1 "APHHS1005CGCK" APHHS1005_Green 2409.03,3912.62 r0 top value=Green
LD2 "APHHS1005CGCK" APHHS1005_Green 5243.74,3658.94 r180 top value=Green
LD3 "APHHS1005CGCK" APHHS1005_Green 4447.13,4258.79 r90 top value=Green
LD5 "APHHS1005CGCK" APHHS1005_Green 5458.65,4393.42 r270 top value=Green
NT1 "Net-Tie" Net-Tie_50milWide_30milLong 3331.11,4007.12 r180 top net-tie
NT2 "Net-Tie" Net-Tie_50milWide_30milLong 3212.01,4007.12 r0 top net-tie
NT3 "Net-Tie" Net-Tie_50milWide_30milLong 3271.56,4064.09 r90 top net-tie
NT4 "Net-Tie" Net-Tie_50milWide_30milLong 3271.56,3958.52 r90 top net-tie
Q1 "BSS123-7-F" FP-BSS123-7-F_SOT23-IPC_C 5378.17,4367.71 r0 top
Q2 "BSS123" SOT-23 3490.95,4433.69 r180 top value=100V
R1 "MCT06030Z0000ZP500" 0603 5459.72,4152.95 r180 top value=0
R2 "RC0201JR-070RL" "FP-RC0201JR-070RL_0201 (0603 Metric)-MFG" 4295.7,4110.3 r270 bottom
R3 "RR0306P-103-D" FP-RR0306P-103-D_0201-IPC_C#1 3802,3912.22 r180 bottom
R4 "CRCW0201100KFKED" 0201L 3718.75,4394.61 r180 top value=100k
R5 "CRCW0201100KFKED" 0201L 4378.13,4374.27 r270 top value=100k
R6 "CRCW020133R2FNED" 0201L 3706.27,4022.49 r270 bottom value=33.2
R9 "CRCW0201100KFKED" 0201L 3835,3920.2 r270 bottom value=100k
R13 "RC0201JR-07220RL" 0201L 5249.72,3687.65 r0 top value=220
R16 "RC0201FR-077K87L" 0201L 4591.03,4385.42 r180 bottom value=7.87k
R17 "CRCW0402330KFKED" 0402L 4554.01,3796.66 r270 top value=330k
R18 "ERJ-2GE0R00X" 0402 5561.26,4092.41 r270 top value=0
R20 "CRCW040249K9FKED" 0402L 5366.79,3993.44 r270 top value=49.9k
R21 "RR0306P-103-D" FP-RR0306P-103-D_0201-IPC_C#1 4318.97,4310.76 r0 bottom
R22 "RR0306P-103-D" FP-RR0306P-103-D_0201-IPC_C#1 4318.97,4288.76 r0 bottom
R23 "RR0306P-103-D" FP-RR0306P-103-D_0201-IPC_C#1 4301.24,4249.29 r0 bottom
R24 "CRCW0402100KFKED" 0402L 5562.22,3981.07 r90 top value=100k
R27 "CRCW040230K0FKED" 0402L 5488.05,3893.28 r0 top value=30.0k
R29 "CRCW0402330KFKED" 0402L 4609.94,3796.66 r90 top value=330k
R30 "ERJ-2GE0R00X" 0402 5262.71,3809.65 r90 top locked value=0
R38 "ERJ-2GE0R00X" 0402 5172.01,3761.87 r180 top value=0
R39 "ERJ-2GEJ101X" 0402L 4644.55,4627.32 r90 top value=100
R42 "RC0201JR-07220RL" 0201L 4479.55,4261.12 r270 top value=220
R43 "RR0306P-103-D" FP-RR0306P-103-D_0201-IPC_C#1 3630.7,3875.43 r0 bottom
R44 "RR0306P-103-D" FP-RR0306P-103-D_0201-IPC_C#1 3619.37,4059.85 r0 bottom
R45 "RR0306P-103-D" FP-RR0306P-103-D_0201-IPC_C#1 3809.22,3978.91 r0 bottom
R46 "CRCW020133R2FNED" 0201L 3585.62,3878.26 r0 bottom value=33.2
R47 "CRCW020133R2FNED" 0201L 3734.37,4022.49 r270 bottom value=33.2
R48 "CRCW020133R2FNED" 0201L 3608.37,4021.09 r270 bottom value=33.2
R49 "CRCW020133R2FNED" 0201L 3777.55,3952.24 r270 bottom value=33.2
R51 "ERJ-2GE0R00X" 0402 5170.22,3816.05 r0 top value=0
R57 "ERJ-2GE0R00X" 0402 4682.66,4626.31 r90 top value=0
R59 "RR0306P-103-D" FP-RR0306P-103-D_0201-IPC_C#1 4301.24,4224.76 r0 bottom
R63 "ERJ-2GE0R00X" 0402 5262.71,3916.9 r90 top value=0
R64 "RC0201FR-074K99L" 0201L 2422.86,4069.66 r0 bottom value=4.99k
R65 "RR0306P-103-D" FP-RR0306P-103-D_0201-IPC_C#1 2451.72,4059 r90 bottom
R66 "CRCW020133R2FNED" 0201_Silk 5053.82,3962.19 r180 bottom value=33.2
R67 "CRCW020133R2FNED" 0201_Silk 5053.5,3993.15 r180 bottom value=33.2
R68 "CRCW040249R9FKED" 0402L 5080.69,4558.28 r0 top value=49.9
R69 "CRCW020133R2FNED" 0201_Silk 5053.48,4029.42 r180 bottom value=33.2
R70 "CRCW020133R2FNED" 0201_Silk 5206.3,4070.76 r90 top value=33.2
R71 "CRCW02010000Z0ED" 0201_Silk 4972.14,3793.56 r90 top value=0
R72 "CRCW04021K00FKED" 0402L 5214.37,4445.81 r90 top value=1.00k
R73 "CRCW04021K00FKED" 0402L 5247.02,4387.04 r0 top value=1.00k
R74 "CRCW04021K00FKED" 0402L 5248.83,4354.19 r0 top value=1.00k
R75 "RC0201JR-071KL" 0201L 3869.6,3903.22 r270 bottom value=1.0k
R76 "CRCW04021K00FKED" 0402L 5073.68,4350.83 r270 bottom value=1.00k
R77 "RR0306P-103-D" FP-RR0306P-103-D_0201-IPC_C#1 3579.3,4457.3 r180 bottom
R78 "RR0306P-103-D" FP-RR0306P-103-D_0201-IPC_C#1 3579.29,4474.55 r180 bottom
R80 "RR0306P-103-D" FP-RR0306P-103-D_0201-IPC_C#1 3579.36,4440.29 r180 bottom
R81 "RR0306P-103-D" FP-RR0306P-103-D_0201-IPC_C#1 3579.46,4508.82 r180 bottom
R82 "RR0306P-103-D" FP-RR0306P-103-D_0201-IPC_C#2 3579.46,4491.64 r180 bottom
R83 "RR0306P-103-D" FP-RR0306P-103-D_0201-IPC_C#1 4277.8,4155.3 r180 bottom
R84 "RR0306P-103-D" FP-RR0306P-103-D_0201-IPC_C#1 4119.89,3922.4 r0 bottom
R85 "RR0306P-103-D" FP-RR0306P-103-D_0201-IPC_C#1 4355.44,4224.99 r0 bottom
R87 "CRCW040210K0FKED" 0402L 4990.81,4549.28 r180 top value=10.0k
R89 "CRCW04021K00FKED" 0402L 4704.82,3810.11 r90 top value=1.00k
R90 "CRCW04024K87FKED" 0402L 5249.44,4318.34 r180 top value=4.87k
R91 "ERJ-2GE0R00X" 0402L 3469.07,3967.81 r180 bottom value=0
R92 "ERJ-2GE0R00X" 0402L 3357.44,4089.35 r270 bottom value=0
R93 "RR0306P-103-D" FP-RR0306P-103-D_0201-IPC_C#1 3536.62,4457.3 r180 bottom
R94 "ERJ-2GE0R00X" 0402L 3092.37,4085.88 r0 top value=0
R95 "CRCW04021K00FKED" 0402 3456.57,4052.72 r180 bottom value=1.00k
R96 "RR0306P-103-D" FP-RR0306P-103-D_0201-IPC_C#1 3536.62,4440.29 r180 bottom
R97 "RC0402FR-0710KL" FP-RC0402FR-0710KL_0402-MFG 3450.38,4016.69 r180 bottom value=10k
R98 "RR0306P-103-D" FP-RR0306P-103-D_0201-IPC_C#1 3536.62,4474.39 r180 bottom
R103 "RC0201JR-070RL" "FP-RC0201JR-070RL_0201 (0603 METRIC)-IPC_C" 4355.64,4245.1 r0 bottom
R104 "ERJ-2GEJ511X" 0402L 3513.31,4533.92 r0 top value=510
R105 "RC0201JR-07510RL" 0201L 2358.26,3931.95 r270 top value=510
R106 "ERJ-2GEJ511X" 0402L 3618.22,4396.48 r180 top value=510
R107 "RC0201JR-07510RL" 0201L 5490.33,4396.73 r90 top value=510
R108 "RC0201JR-07510RL" 0201L 5332.79,4068.68 r0 top value=510
R109 "RC0201JR-070RL" "FP-RC0201JR-070RL_0201 (0603 Metric)-MFG" 3743.83,4023.9 r270 top
R110 "CRCW04024K99FKED" 0402 2685.12,4113.26 r180 top value=4.99k
R111 "RC0201JR-07220RL" 0201L 5195.28,3687.32 r0 top value=220
R112 "CRCW0402100KFKED" 0402L 3618.22,4348.49 r0 top value=100k
R113 "Rpg" 0603L 2605.99,4097.47 r90 top value=100k
R114 "Rflt" 0603L 2961.66,4131.16 r180 top value=49.9k
R115 "ERJ-2GE0R00X" 0402L 2620.02,4153.26 r270 bottom value=0
R118 "RC0201JR-070RL" "FP-RC0201JR-070RL_0201 (0603 Metric)-MFG" 3476.67,4114.4 r90 bottom
R119 "CRCW0201100KFKED" 0201L 3510.55,4100.58 r180 bottom value=100k
R120 "HCJ0603ZT0R00" FP-HCJ0603ZT0R00_0603-MFG 3269.27,4615.45 r180 top value=0
R121 "ERJ-2GE0R00X" 0402L 3484.04,3773.64 r180 top value=0
R122 "CRCW0402100KFKED" 0402L 3112.06,4124.03 r180 top value=100k
R123 "CRCW040210K0FKED" 0402L 3192.2,4103.14 r270 bottom value=10.0k
R124 "RR0306P-103-D" FP-RR0306P-103-D_0201-IPC_C#1 5318.65,4126.65 r270 top
R125 "RR0306P-103-D" FP-RR0306P-103-D_0201-IPC_C#1 4946.75,3678.43 r0 top
R126 "ERJ-2GE0R00X" 0402L 3124.79,3794.57 r270 bottom value=0
R127 "ERJ-2GE0R00X" 0402L 3112.06,3891.22 r90 top value=0
R128 "ERJ-2GE0R00X" 0402L 3115.49,4208.74 r90 bottom value=0
R129 "RC0201JR-070RL" "FP-RC0201JR-070RL_0201 (0603 METRIC)-IPC_C" 4947.46,3652.08 r180 top
R131 "ERJ-2GE0R00X" 0402L 3072.69,3881.17 r90 top value=0
R134 "ERJ-2GE0R00X" 0402L 3414.2,3887.48 r0 top value=0
R136 "ERJ-2GE0R00X" 0402L 3403.94,4102.98 r90 top value=0
R139 "CRCW040233R2FKED" 0402 3474.62,3913.28 r180 bottom value=33.2
R141 "CRCW04022K20JNED" 0402 3476.67,3966.37 r0 top value=2.2k
R158 "RC0201FR-0782K5L" 0201L 4228.2,4119.6 r0 bottom value=82.5k
R159 "RC0201JR-07750RL" 0201L 4223.5,4078.1 r270 bottom value=750
R170 "RC0201FR-0782K5L" 0201L 4154.35,3946.46 r180 bottom value=82.5k
R171 "RC0201JR-07750RL" 0201L 4204.44,3980.18 r0 bottom value=750
R172 "RC0201FR-0782K5L" 0201L 4401.11,4142.03 r90 bottom value=82.5k
R174 "RC0201FR-077K87L" 0201L 4269.1,4113.8 r90 bottom value=7.87k
R176 "RC0201FR-077K87L" 0201L 4389.6,4181.8 r0 bottom value=7.87k
R177 "RR0306P-103-D" FP-RR0306P-103-D_0201-IPC_C#1 5206.87,4127.92 r270 top
R178 "RR0306P-103-D" FP-RR0306P-103-D_0201-IPC_C#1 5257.9,4054.09 r180 top
S1 "218-4LPST" SW_218-4LPST 4647.7,4183.33 r90 bottom
S3 "CHS-01TA" FP-CHS-01TA_SMT_SW_5MM4_2MM5-MFG 4378.13,3983.7 r270 bottom
SW2 "B3U-1000P" SW_B3U-1000P 5287.75,4211.95 r180 top
SW3 "B3U-1000P" SW_B3U-1000P 5073.11,3669.47 r0 top
TP1 "TESTPOINT" TP_25MIL-SMT#1 2540.97,4123.57 r90 top
TP2 "TESTPOINT" TP_25MIL-SMT#1 3810.59,4141.77 r90 bottom
TP3 "TESTPOINT" TP_25MIL-SMT#1 3784,4092.76 r90 bottom
TP4 "TESTPOINT" TP_25MIL-SMT#1 2646.13,4069.66 r90 top
TP5 "TESTPOINT" TP_VIA_060RND040 4923.05,3792.76 r180 top
TP6 "TESTPOINT" TP_25MIL-SMT#1 4313,4390.94 r0 bottom
TP7 "TESTPOINT" TP_25MIL-SMT#1 4280.69,4391.59 r270 bottom
TP8 "TESTPOINT" TP_25MIL-SMT#1 4252.7,4332.6 r90 bottom
TP9 "TESTPOINT" TP_25MIL-SMT#1 4217.3,4366.19 r90 bottom
TP10 "TESTPOINT" TP_25MIL-SMT#1 3072.69,3937.64 r90 top
TP11 "TP_SM_1MM" TP_SM_1MM 4383.28,3924.67 r90 top
TP12 "TESTPOINT" TP_VIA_060RND040 3583.71,4214.86 r90 top
TP14 "TESTPOINT" TP_25MIL-SMT#1 4294.6,4337.1 r180 bottom
TP15 "TESTPOINT" TP_25MIL-SMT#1 3488.75,4502.59 r270 bottom
TP16 "TESTPOINT" TP_25MIL-SMT#1 3557.51,4156.76 r0 top
TP17 "TESTPOINT" TP_25MIL-SMT#1 3689.3,4268.85 r270 top
TP20 "4953" FP-4953_HDR1-MFG 2336.5,4405.06 r90 top
TP22 "TESTPOINT" TP_25MIL-SMT#1 3484.04,4083.73 r270 top
TP23 "TESTPOINT" TP_25MIL-SMT#2 3594.89,3782.36 r90 top
TP24 "TESTPOINT" TP_25MIL-SMT#1 3655,3849.49 r90 top
U2 "XI6843ARQGALP" ALP0180A 4056.48,4141.61 r90 top
U4 "TPS79601DRBR" DRB0008B 5465.42,3979.58 r0 top
U5 "TM4C1294NCPDTT3" PDT0128A 4854.03,4188.87 r90 top
U6 "LM4040C25QDBZR" DBZ0003A_N 4791.67,3694.89 r0 top
U8 "LM68635SCRZTRQ1" RZT0020A-MFG 2771.82,4240.39 r90 top
U9 "MX25R1635FZUIH0" USON-8L 3680.29,3934.68 r0 bottom
U10 "LP877451A1RXVRQ1" RXV0028A-MFG 3271.56,4012.04 r180 top
U16 "SN74LVC1G11DSFR" DSF0006A-MFG 5268.67,4097.87 r0 top
Y1 "CX2016DB40000D0FLJCC" FP-CX2016DB40000D0FLJCC_SMT_2MM0_1MM6-MFG 3650.74,4037.45 r0 top
Y2 "ECS-160-8-33Q-RES-TR" FP-ECS-160-8-33Q-RES-TR_SMT4_3MM2_2MM5-MFG 4818.81,4607.2 r180 top
Y4 "ABS05W-32.768KHZ-D-2-T" FP-ABS05W-32.768KHZ-D-2-T_XTAL_SMT_1MM6_1MM0-MFG 3431.38,4456.43 r270 bottom
ZZ1 "This Assembly Note is for PCB labels only" AssemblyNoteLabel 2349.62,2814.36 r0 top
ZZ2 "These assemblies are ESD sensitive, ESD precautions shall be observed." AssemblyNote 2346.49,2738.89 r0 top
ZZ3 "These assemblies must be clean and free from flux and all contaminants. Use of no clean flux is not acceptable." AssemblyNote 2346.43,2653.5 r0 top
ZZ4 "These assemblies must comply with workmanship standards IPC-A-610 Class 2, unless otherwise specified." AssemblyNote 2343.34,2567.2 r0 top
ZZ5.1 "Cut the thermal pad(Part Number#GPVOUS-0.125-AC-0816) for the shape and size of the inner surface of the heatsink(Part Number#MCH054) and paste it on the inner surface of the heatsink;" AssemblyNote 2340.76,2492.7 r0 top
ZZ5.2 "Bring the heatsink onto the PCB bottom side (Opposite side of AOP device). Match the teeth in the heatsink with break-away area in the PCB and press the heatsink onto the PCB slightly so as thermal pad is spread all over the area" AssemblyNote 2343.41,2409 r0 top

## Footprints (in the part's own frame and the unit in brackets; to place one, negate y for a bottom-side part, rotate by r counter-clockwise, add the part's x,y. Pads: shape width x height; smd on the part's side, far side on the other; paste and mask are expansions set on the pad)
0201_033L [mm] "0201"
  rect 0.36x0.32 smd mask+0.048: 1(-0.28,0) 2(0.28,0)
  body extent -0.31,-0.16 0.31,0.16, height 0.33
0201_Silk [mm] "Data from Kemet datasheet CC101_COM dated 7/28/11"
  rect 0.46x0.42 smd mask+0.048: 1(-0.33,0) 2(0.33,0)
  silkscreen extent -0.75,-0.4 0.75,0.4, body extent -0.31,-0.16 0.31,0.16, height 0.26
0201L [mm] "Data from Kemet datasheet CC101_COM dated 7/28/11"
  rect 0.36x0.32 smd mask+0.048: 1(-0.28,0) 2(0.28,0)
  body extent -0.31,-0.16 0.31,0.16, height 0.26
0402 [mm] "0402 from SM-752 data"
  rect 0.8x0.6 smd: 1(-0.6,0) 2(0.6,0)
  silkscreen extent -1.22,-0.52 1.22,0.52, body extent -0.55,-0.3 0.55,0.3, height 0.6
0402_065L [mm] "0402"
  rect 0.6x0.5 smd: 1(-0.5,0) 2(0.5,0)
  body extent -0.55,-0.3 0.55,0.3, height 0.65
0402_070 [mil] "SMD, 2-Leads, Body 1.2x0.7mm, Height 0.7mm"
  rect 15x24 smd: 1(-20,0) 2(20,0)
  body extent -24,-14 24,14, height 28
0402L [mm] "0402 from SM-752 data"
  rect 0.6x0.5 smd: 1(-0.5,0) 2(0.5,0)
  body extent -0.55,-0.3 0.55,0.3, height 0.6
0603 [mm] "0603 from SM-752 data"
  rect 1x0.95 smd: 1(-0.8,0) 2(0.8,0)
  silkscreen extent -1.52,-0.69 1.52,0.69, body extent -0.87,-0.47 0.87,0.47, height 1
0603L [mm] "0603 from SM-752 data"
  rect 0.8x0.85 smd: 1(-0.7,0) 2(0.7,0)
  silkscreen extent -0.07,-0.33 0.07,0.33, body extent -0.87,-0.47 0.87,0.47, height 1
0805L [mm] "0805 from SM-752 data"
  rect 1.1x1.4 smd: 1(-0.75,0) 2(0.75,0)
  body extent -1.1,-0.72 1.1,0.72, height 1.45
1210_220 [mm] "1210"
  rect 1.3x2.7 smd: 1(-1.45,0) 2(1.45,0)
  silkscreen extent -2.32,-1.57 2.32,1.57, body extent -1.7,-1.35 1.7,1.35, height 2.2
1210_280 [mm] "SMD, 2-Leads, Body 3.6x2.8mm, Height 2.8mm"
  rect 1.1x2.2 smd: 1(-1.65,0) 2(1.65,0)
  silkscreen extent -0.84,-1.4 0.84,1.4, body extent -1.8,-1.4 1.8,1.4, height 2.8
ALP0180A [mm] "BGA-180"
  round 0.4 smd: A1(-6.8,6.8) A2(-6,6.8) A3(-5.2,6.8) A4(-4.4,6.8) A5(-3.6,6.8) A6(-2.8,6.8) A7(-2,6.8) A8(-1.2,6.8) A9(-0.4,6.8) A10(0.4,6.8) A11(1.2,6.8) A12(2,6.8) A13(2.8,6.8) A14(3.6,6.8) A15(4.4,6.8) A16(5.2,6.8) A17(6,6.8) A18(6.8,6.8) B1(-6.8,6) B2(-6,6) B3(-5.2,6) B4(-4.4,6) B5(-3.6,6) B6(-2.8,6) B7(-2,6) B8(-1.2,6) B9(-0.4,6) B10(0.4,6) B11(1.2,6) B12(2,6) B13(2.8,6) B14(3.6,6) B15(4.4,6) B16(5.2,6) B17(6,6) B18(6.8,6) C1(-6.8,5.2) C2(-6,5.2) C3(-5.2,5.2) C4(-4.4,5.2) C5(-3.6,5.2) C6(-2.8,5.2) C7(-2,5.2) C8(-1.2,5.2) C9(-0.4,5.2) C10(0.4,5.2) C11(1.2,5.2) C12(2,5.2) C13(2.8,5.2) C14(3.6,5.2) C15(4.4,5.2) C16(5.2,5.2) C17(6,5.2) C18(6.8,5.2) D1(-6.8,4.4) D2(-6,4.4) D3(-5.2,4.4) D16(5.2,4.4) D17(6,4.4) D18(6.8,4.4) E1(-6.8,3.6) E2(-6,3.6) E3(-5.2,3.6) E16(5.2,3.6) E17(6,3.6) E18(6.8,3.6) F1(-6.8,2.8) F2(-6,2.8) F3(-5.2,2.8) F16(5.2,2.8) F17(6,2.8) F18(6.8,2.8) G1(-6.8,2) G2(-6,2) G3(-5.2,2) G16(5.2,2) G17(6,2) G18(6.8,2) H1(-6.8,1.2) H2(-6,1.2) H3(-5.2,1.2) H16(5.2,1.2) H17(6,1.2) H18(6.8,1.2) J1(-6.8,0.4) J2(-6,0.4) J3(-5.2,0.4) J16(5.2,0.4) J17(6,0.4) J18(6.8,0.4) K1(-6.8,-0.4) K2(-6,-0.4) K3(-5.2,-0.4) K16(5.2,-0.4) K17(6,-0.4) K18(6.8,-0.4) L1(-6.8,-1.2) L2(-6,-1.2) L3(-5.2,-1.2) L16(5.2,-1.2) L17(6,-1.2) L18(6.8,-1.2) M1(-6.8,-2) M2(-6,-2) M3(-5.2,-2) M16(5.2,-2) M17(6,-2) M18(6.8,-2) N1(-6.8,-2.8) N2(-6,-2.8) N3(-5.2,-2.8) N16(5.2,-2.8) N17(6,-2.8) N18(6.8,-2.8) P1(-6.8,-3.6) P2(-6,-3.6) P3(-5.2,-3.6) P16(5.2,-3.6) P17(6,-3.6) P18(6.8,-3.6) R1(-6.8,-4.4) R2(-6,-4.4) R3(-5.2,-4.4) R16(5.2,-4.4) R17(6,-4.4) R18(6.8,-4.4) T1(-6.8,-5.2) T2(-6,-5.2) T3(-5.2,-5.2) T4(-4.4,-5.2) T5(-3.6,-5.2) T6(-2.8,-5.2) T7(-2,-5.2) T8(-1.2,-5.2) T9(-0.4,-5.2) T10(0.4,-5.2) T11(1.2,-5.2) T12(2,-5.2) T13(2.8,-5.2) T14(3.6,-5.2) T15(4.4,-5.2) T16(5.2,-5.2) T17(6,-5.2) T18(6.8,-5.2) U1(-6.8,-6) U2(-6,-6) U3(-5.2,-6) U4(-4.4,-6) U5(-3.6,-6) U6(-2.8,-6) U7(-2,-6) U8(-1.2,-6) U9(-0.4,-6) U10(0.4,-6) U11(1.2,-6) U12(2,-6) U13(2.8,-6) U14(3.6,-6) U15(4.4,-6) U16(5.2,-6) U17(6,-6) U18(6.8,-6) V1(-6.8,-6.8) V2(-6,-6.8) V3(-5.2,-6.8) V4(-4.4,-6.8) V5(-3.6,-6.8) V6(-2.8,-6.8) V7(-2,-6.8) V8(-1.2,-6.8) V9(-0.4,-6.8) V10(0.4,-6.8) V11(1.2,-6.8) V12(2,-6.8) V13(2.8,-6.8) V14(3.6,-6.8) V15(4.4,-6.8) V16(5.2,-6.8) V17(6,-6.8) V18(6.8,-6.8)
  silkscreen extent -7.5,-7.5 7.5,7.5, body extent -7.5,-7.5 7.5,7.5, height 0.86
APHHS1005_Green [mm] "SMD, 2-Leads, Body 1x0.5mm"
  rrect20% 0.7x0.5 smd: 1(-0.45,0) 2(0.45,0)
  silkscreen extent -0.8,-0.65 1.2,0.65, body extent -0.5,-0.25 0.5,0.25, height 0.5
AssemblyNote [mil] "Assembly Note"
AssemblyNoteLabel [mil] "Assembly Note for PCB Labels"
CONN_105017-0001 [mm] "Molex Micro USB-B"
  rect 0.4x1.35 smd: 1(-1.3,1.35) 2(-0.65,1.35) 3(0,1.35) 4(0.65,1.35) 5(1.3,1.35)
  oval 1.2x1.9 hole 0.6 slot 1.3 at 90 deg: 6(-3.5,-1.35) 9(3.5,-1.35)
  rect 1.5x1.9 smd: 7(-1,-1.35) 8(1,-1.35)
  round 1.45 hole 0.85: 10(2.5,1.35) 11(-2.5,1.35)
  Top Layer region: -3.499,-2.3 -2.299,-2.3 -2.299,-0.4 -3.499,-0.4
  Top Layer region: 3.5,-0.4 2.3,-0.4 2.3,-2.3 3.5,-2.3
  silkscreen extent -4.1,-0.2 4.1,1.4, body extent -4.1,-3.93 4.1,1.5, height 2.72
CONN_UFL-R-SMT-1 [mm] "Hirose recommended land pattern http://www.hirose.co.jp/cataloge_hp/e32119372.pdf 2009.2"
  rect 1.05x1 smd paste-0.1 mask-0.1: 1(-1.525,0)
  rect 2x0.9 on Top Paste: 2(0,1.5) 3(0,-1.5)
  rect 2x0.9 on Top Solder: 2(0,1.5) 3(0,-1.5)
  rect 2.2x1.05 smd paste-2 mask-2: 2(0,1.475) 3(0,-1.475)
  Top Layer keep-out region: -0.801,-0.707 1.099,-0.707 1.099,0.693 -0.801,0.693
  silkscreen extent -1.7,-1.7 1.7,1.7, body extent -1.55,-1.5 1.55,1.5, height 1.27
DBZ0003A_N [mm] "SOT23, 3-Leads, Body 2.9x1.3mm, Pitch 0.95mm, Lead Span 2.4mm, IPC Medium Density"
  rrect17% 1x0.6 smd: 1(-1.2,0.95) 2(-1.2,-0.95) 3(1.2,0)
  silkscreen extent 0.2,-1.5 0.7,1.5, body extent -1.26,-1.46 1.26,1.46, height 0.98
DRB0008B [mm] "SON, 8-Leads, Body 3x3mm, Pitch 0.65mm, Thermal Pad 2.4x1.65mm, TI Recommended"
  rrect33% 0.6x0.3 smd: 1(-1.4,0.975) 2(-1.4,0.325) 3(-1.4,-0.325) 4(-1.4,-0.975) 5(1.4,-0.975) 6(1.4,-0.325) 7(1.4,0.325) 8(1.4,0.975)
  rrect9% 1.47x1.06 on Top Paste: 9(0,-0.63) 9(0,0.63)
  rrect6% 1.65x2.4 smd paste-1.2: 9(0,0)
  silkscreen extent -1.73,-1.73 1.73,1.73, body extent -1.5,-1.5 1.5,1.5, height 0.96
DSF0006A-MFG [mm]
  rrect59% 0.6x0.17 smd paste+0 mask+0: 1(-0.4,0.35) 2(-0.4,0) 3(-0.4,-0.35) 4(0.4,-0.35) 5(0.4,0) 6(0.4,0.35)
  silkscreen extent -1.14,-0.85 0.53,1.02, body extent -0.8,-0.63 0.8,0.63, height 0.25
DSN2_0603 [mm] "SMD, 2-Leads, Body 1.6x0.8mm"
  rect 0.52x0.7 smd: 1(-0.64,0)
  rect 1.05x0.7 smd: 2(0.275,0)
  silkscreen extent -1.4,-0.75 0.8,0.65, body extent -0.8,-0.4 0.8,0.4, height 0.31
Fiducial6.4-20 [mil]
  round 25 smd mask+26.87: 1(0,0)
  Top Layer keep-out circle w46.37: c0,0 r19.68
FP-250R05L120JV4T_0201-IPC_C [mm]
  rrect38% 0.363x0.263 smd paste+0 mask+0: 1(-0.25,0) 2(0.25,0)
  body extent -0.3,-0.15 0.3,0.15, height 0.33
